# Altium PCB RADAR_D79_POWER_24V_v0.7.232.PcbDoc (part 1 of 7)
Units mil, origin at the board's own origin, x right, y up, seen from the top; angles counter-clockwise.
Board outline 3110.24 x 3110.24 mil, 8 copper layers (Top Layer, GND1, SIG1, PWR1, PWR2, SIG2, GND2, Bottom Layer), stack 55.2 mil thick; 304 components, 269 nets, 1408 pads, 1367 vias.
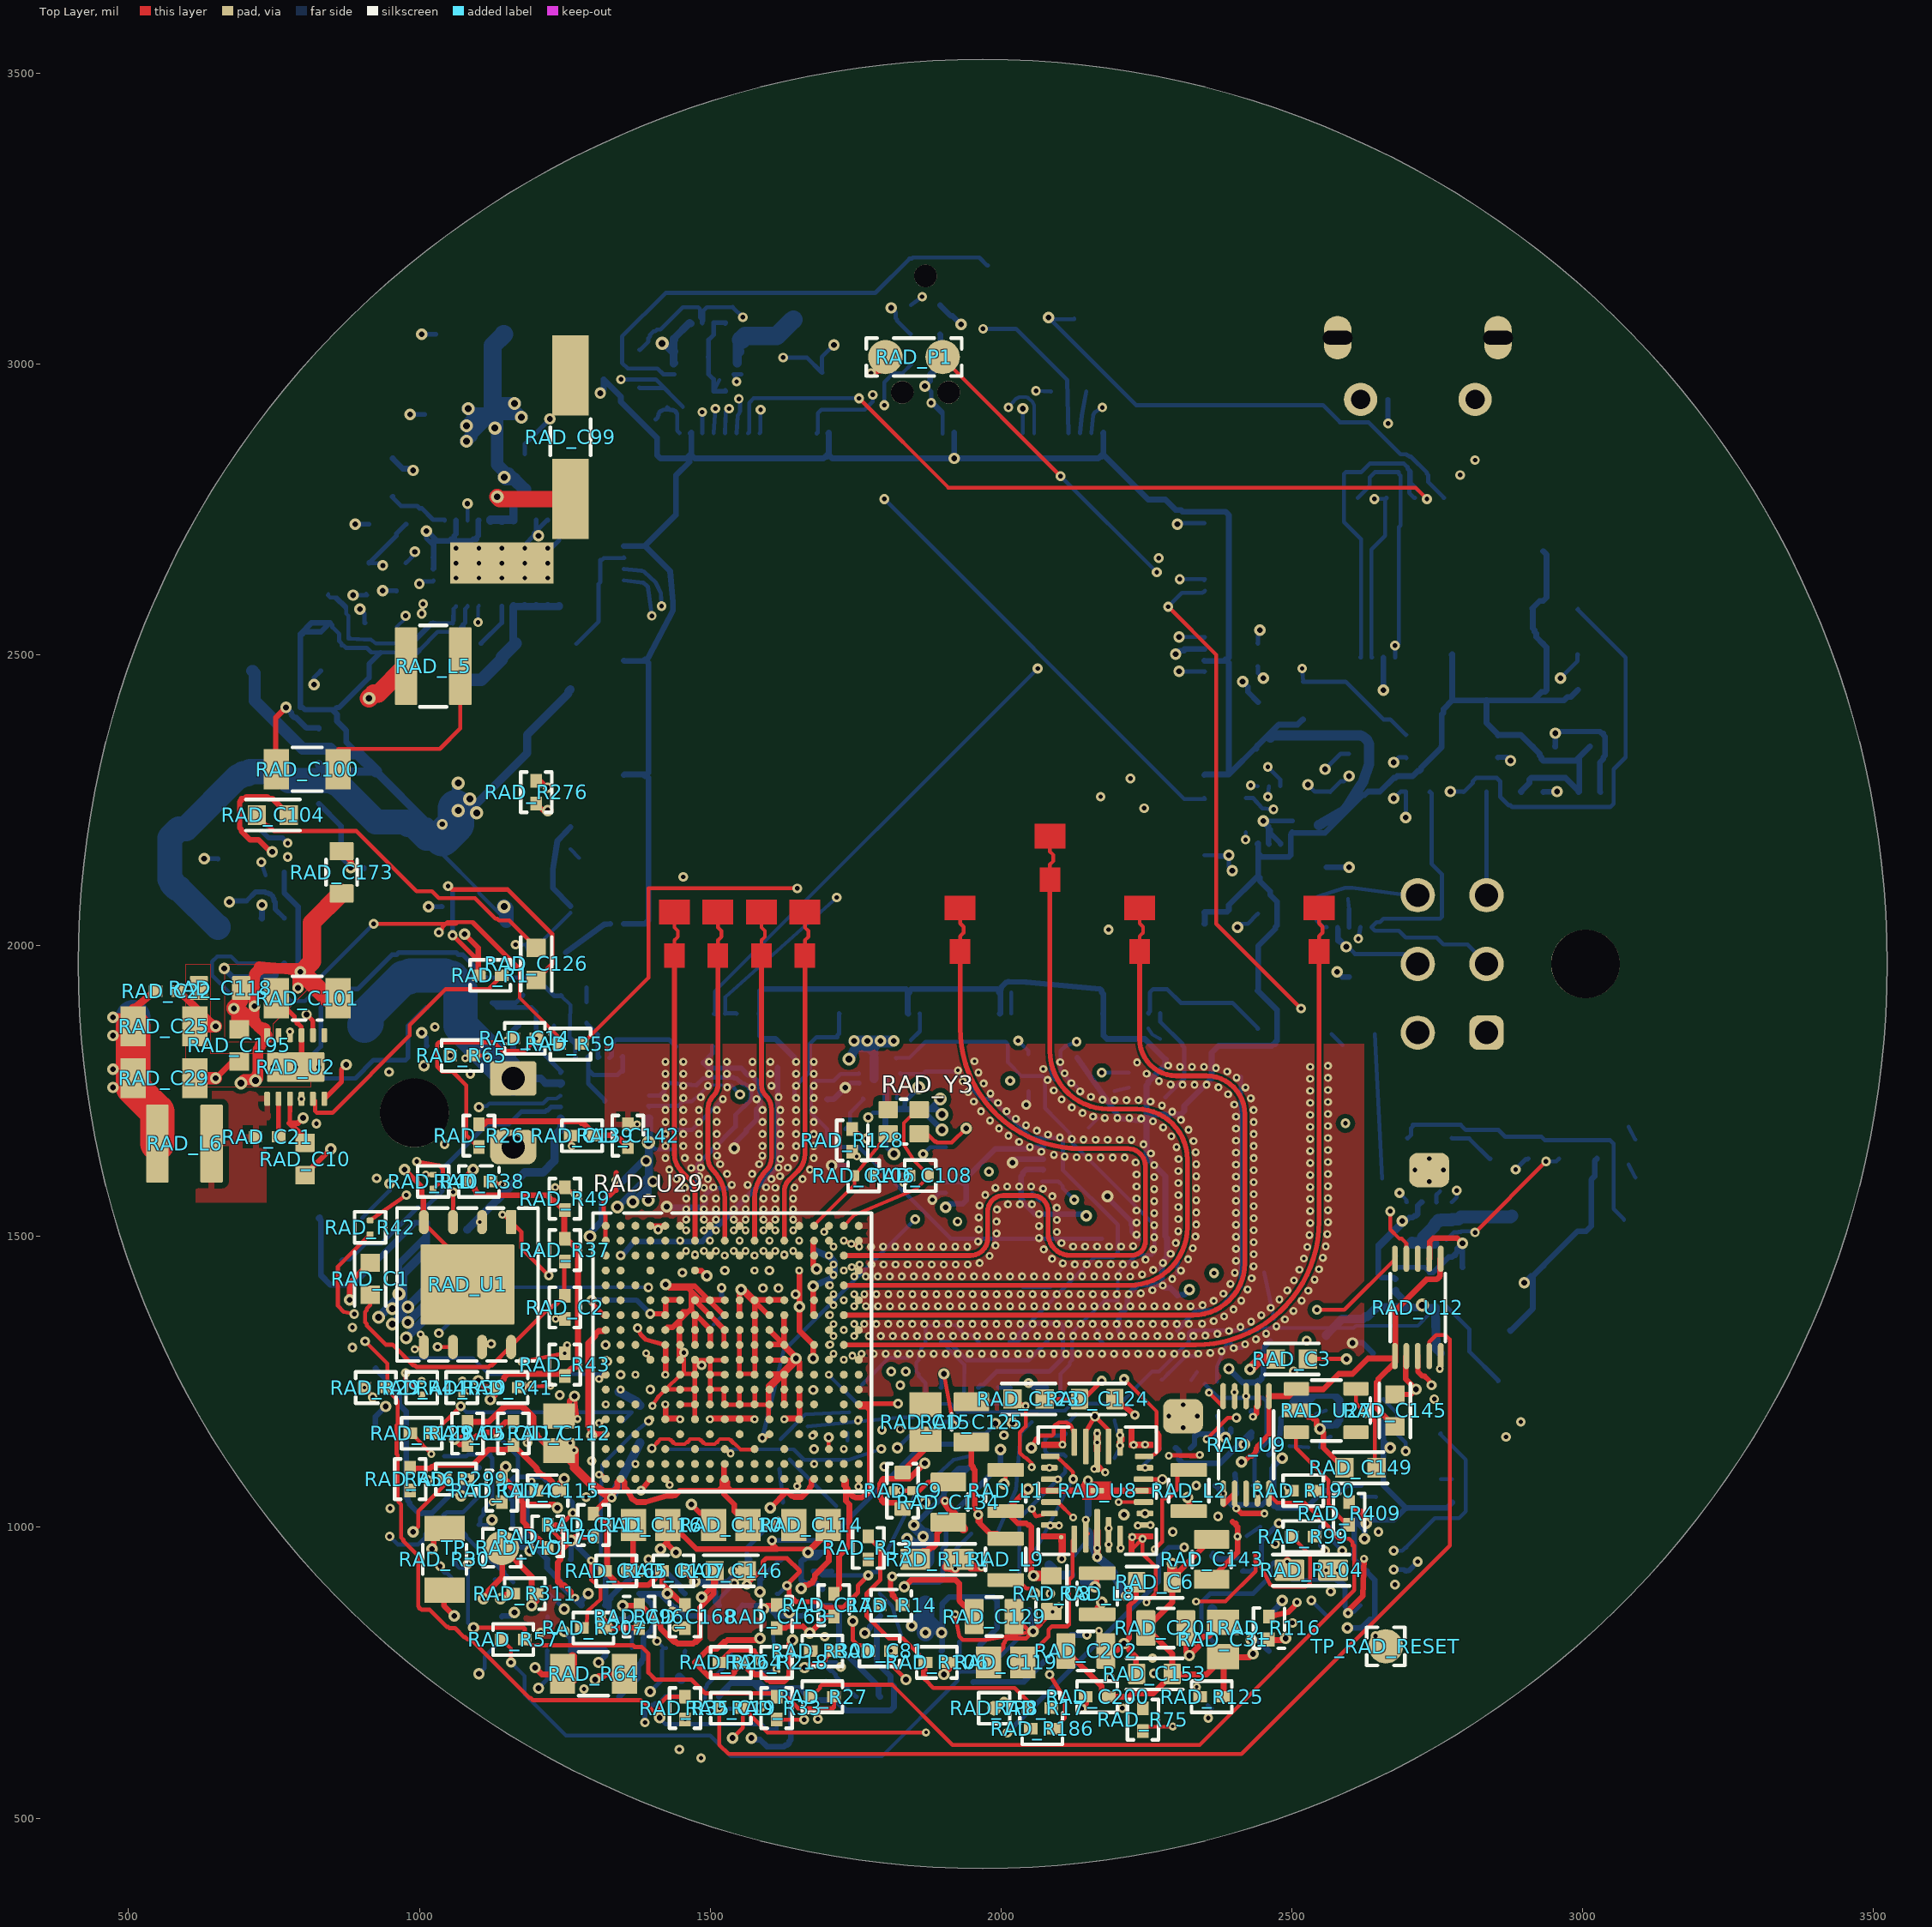
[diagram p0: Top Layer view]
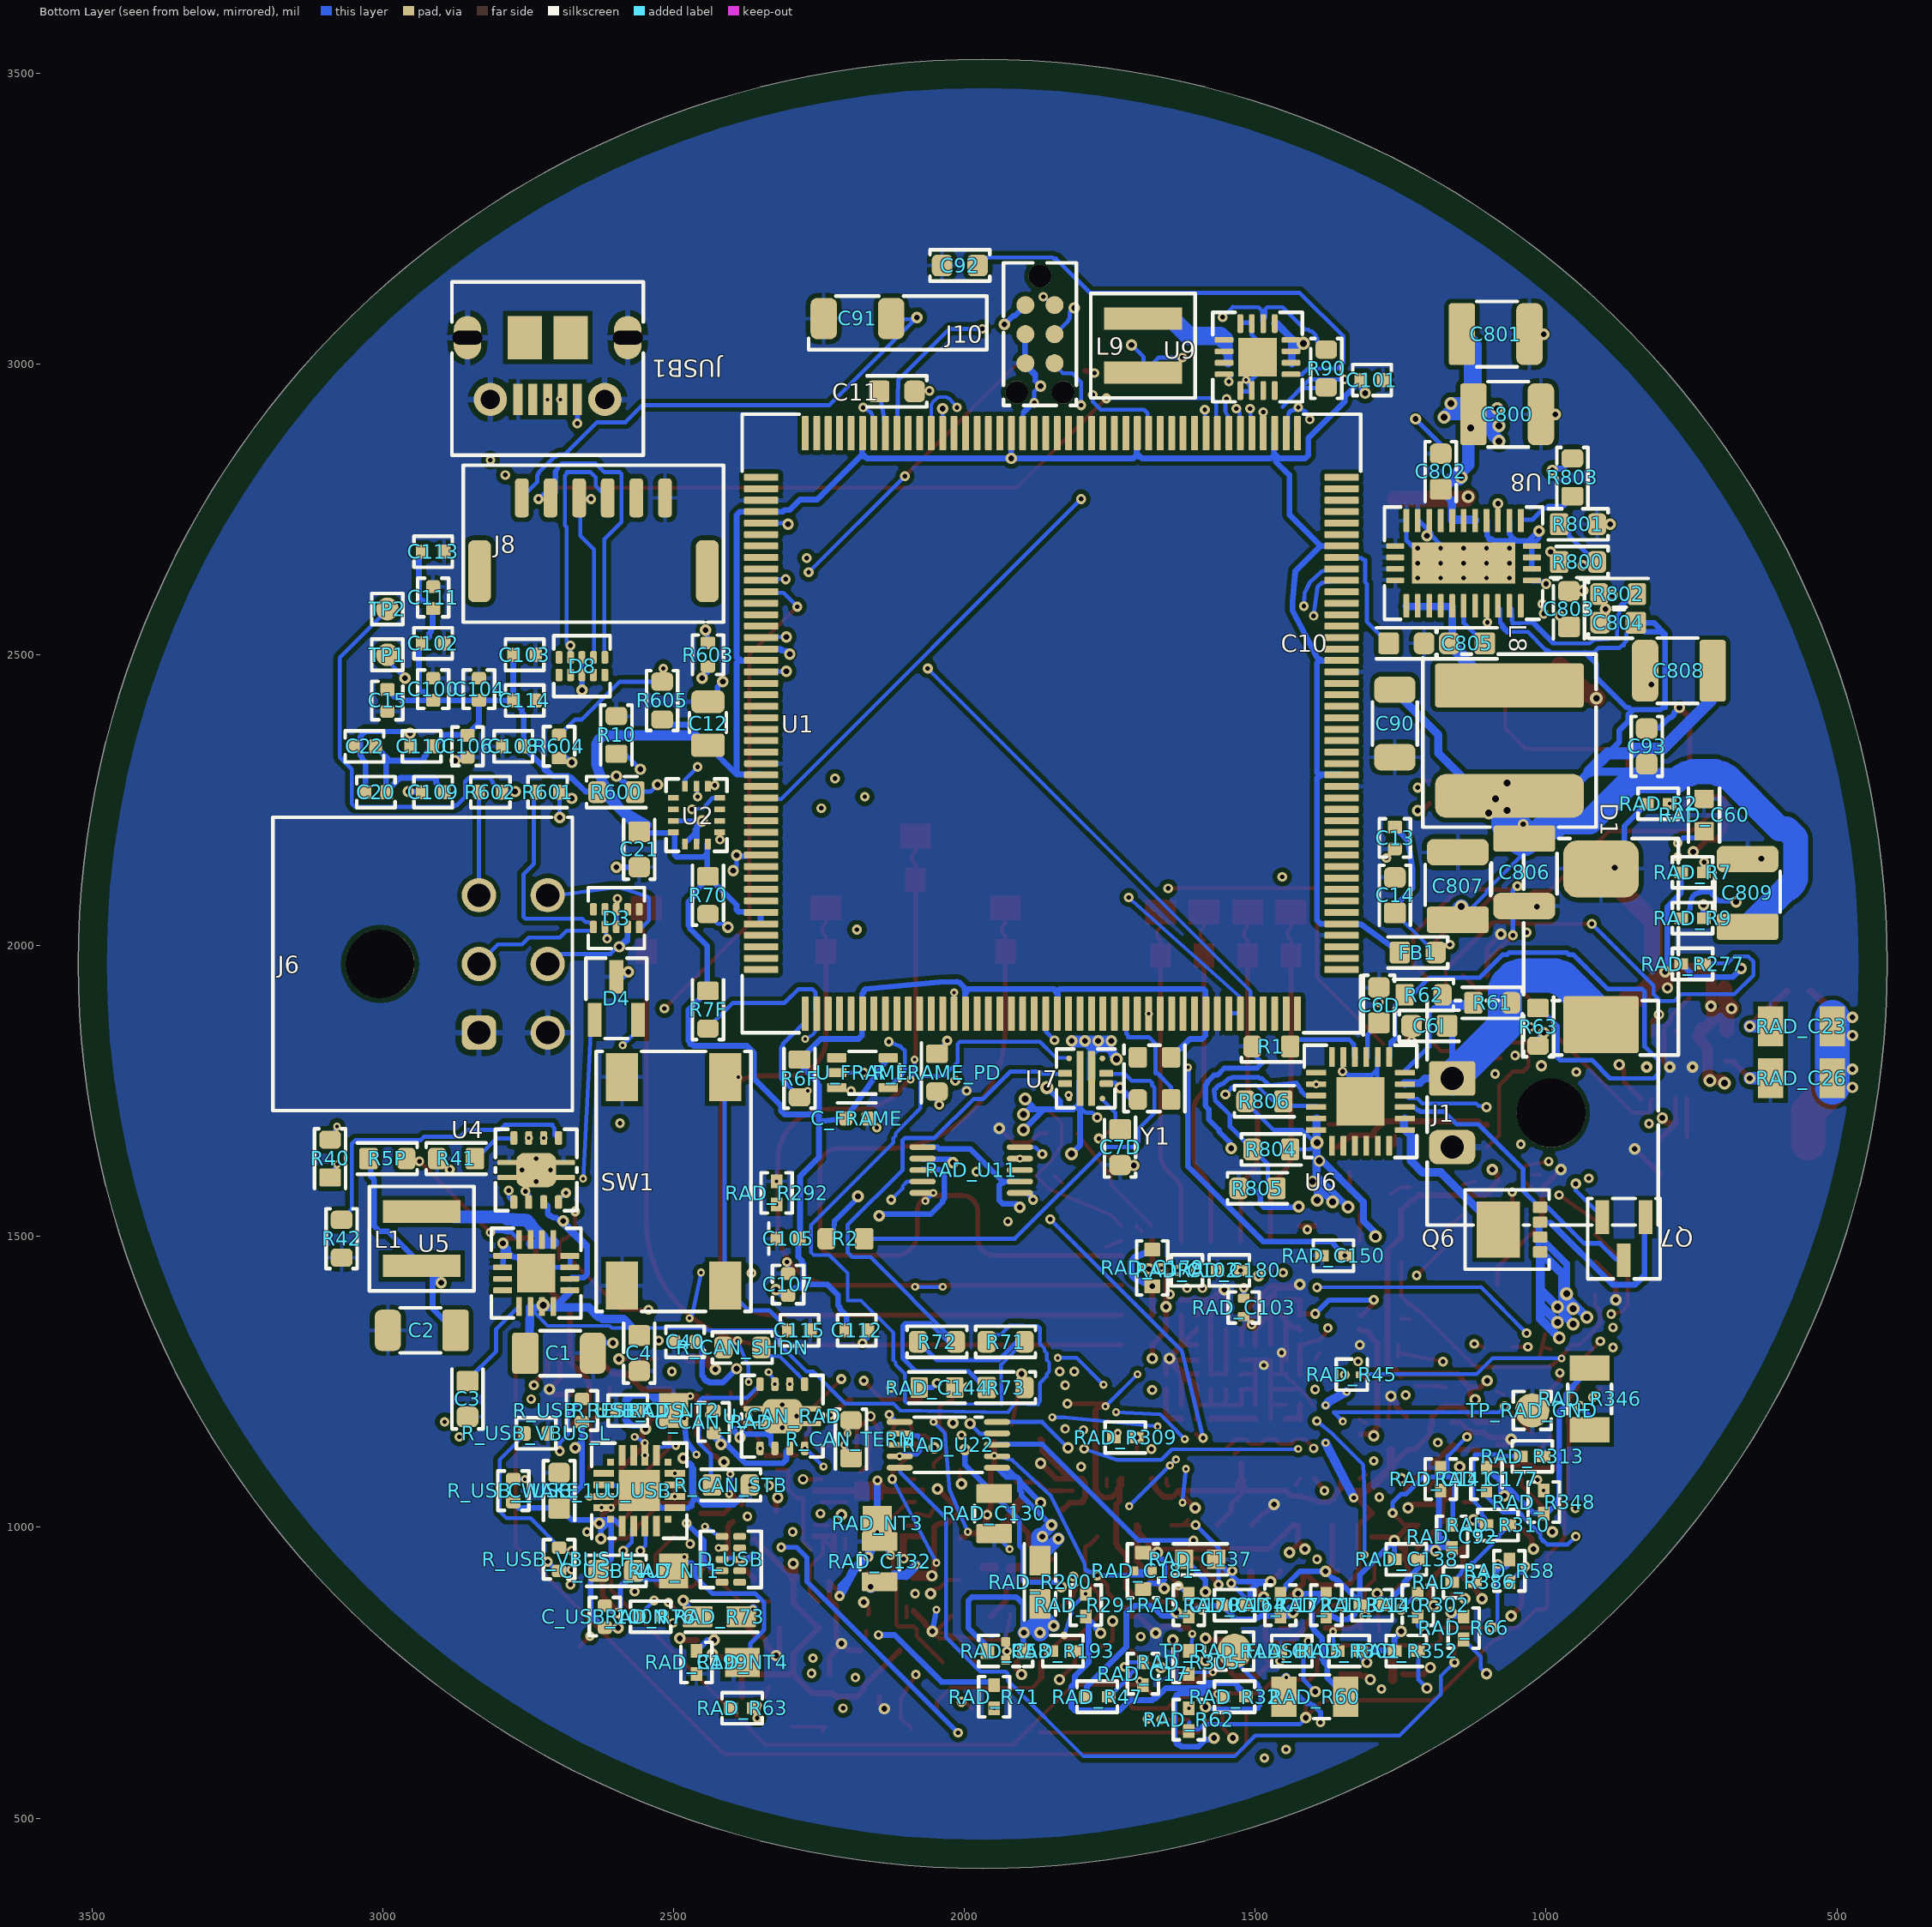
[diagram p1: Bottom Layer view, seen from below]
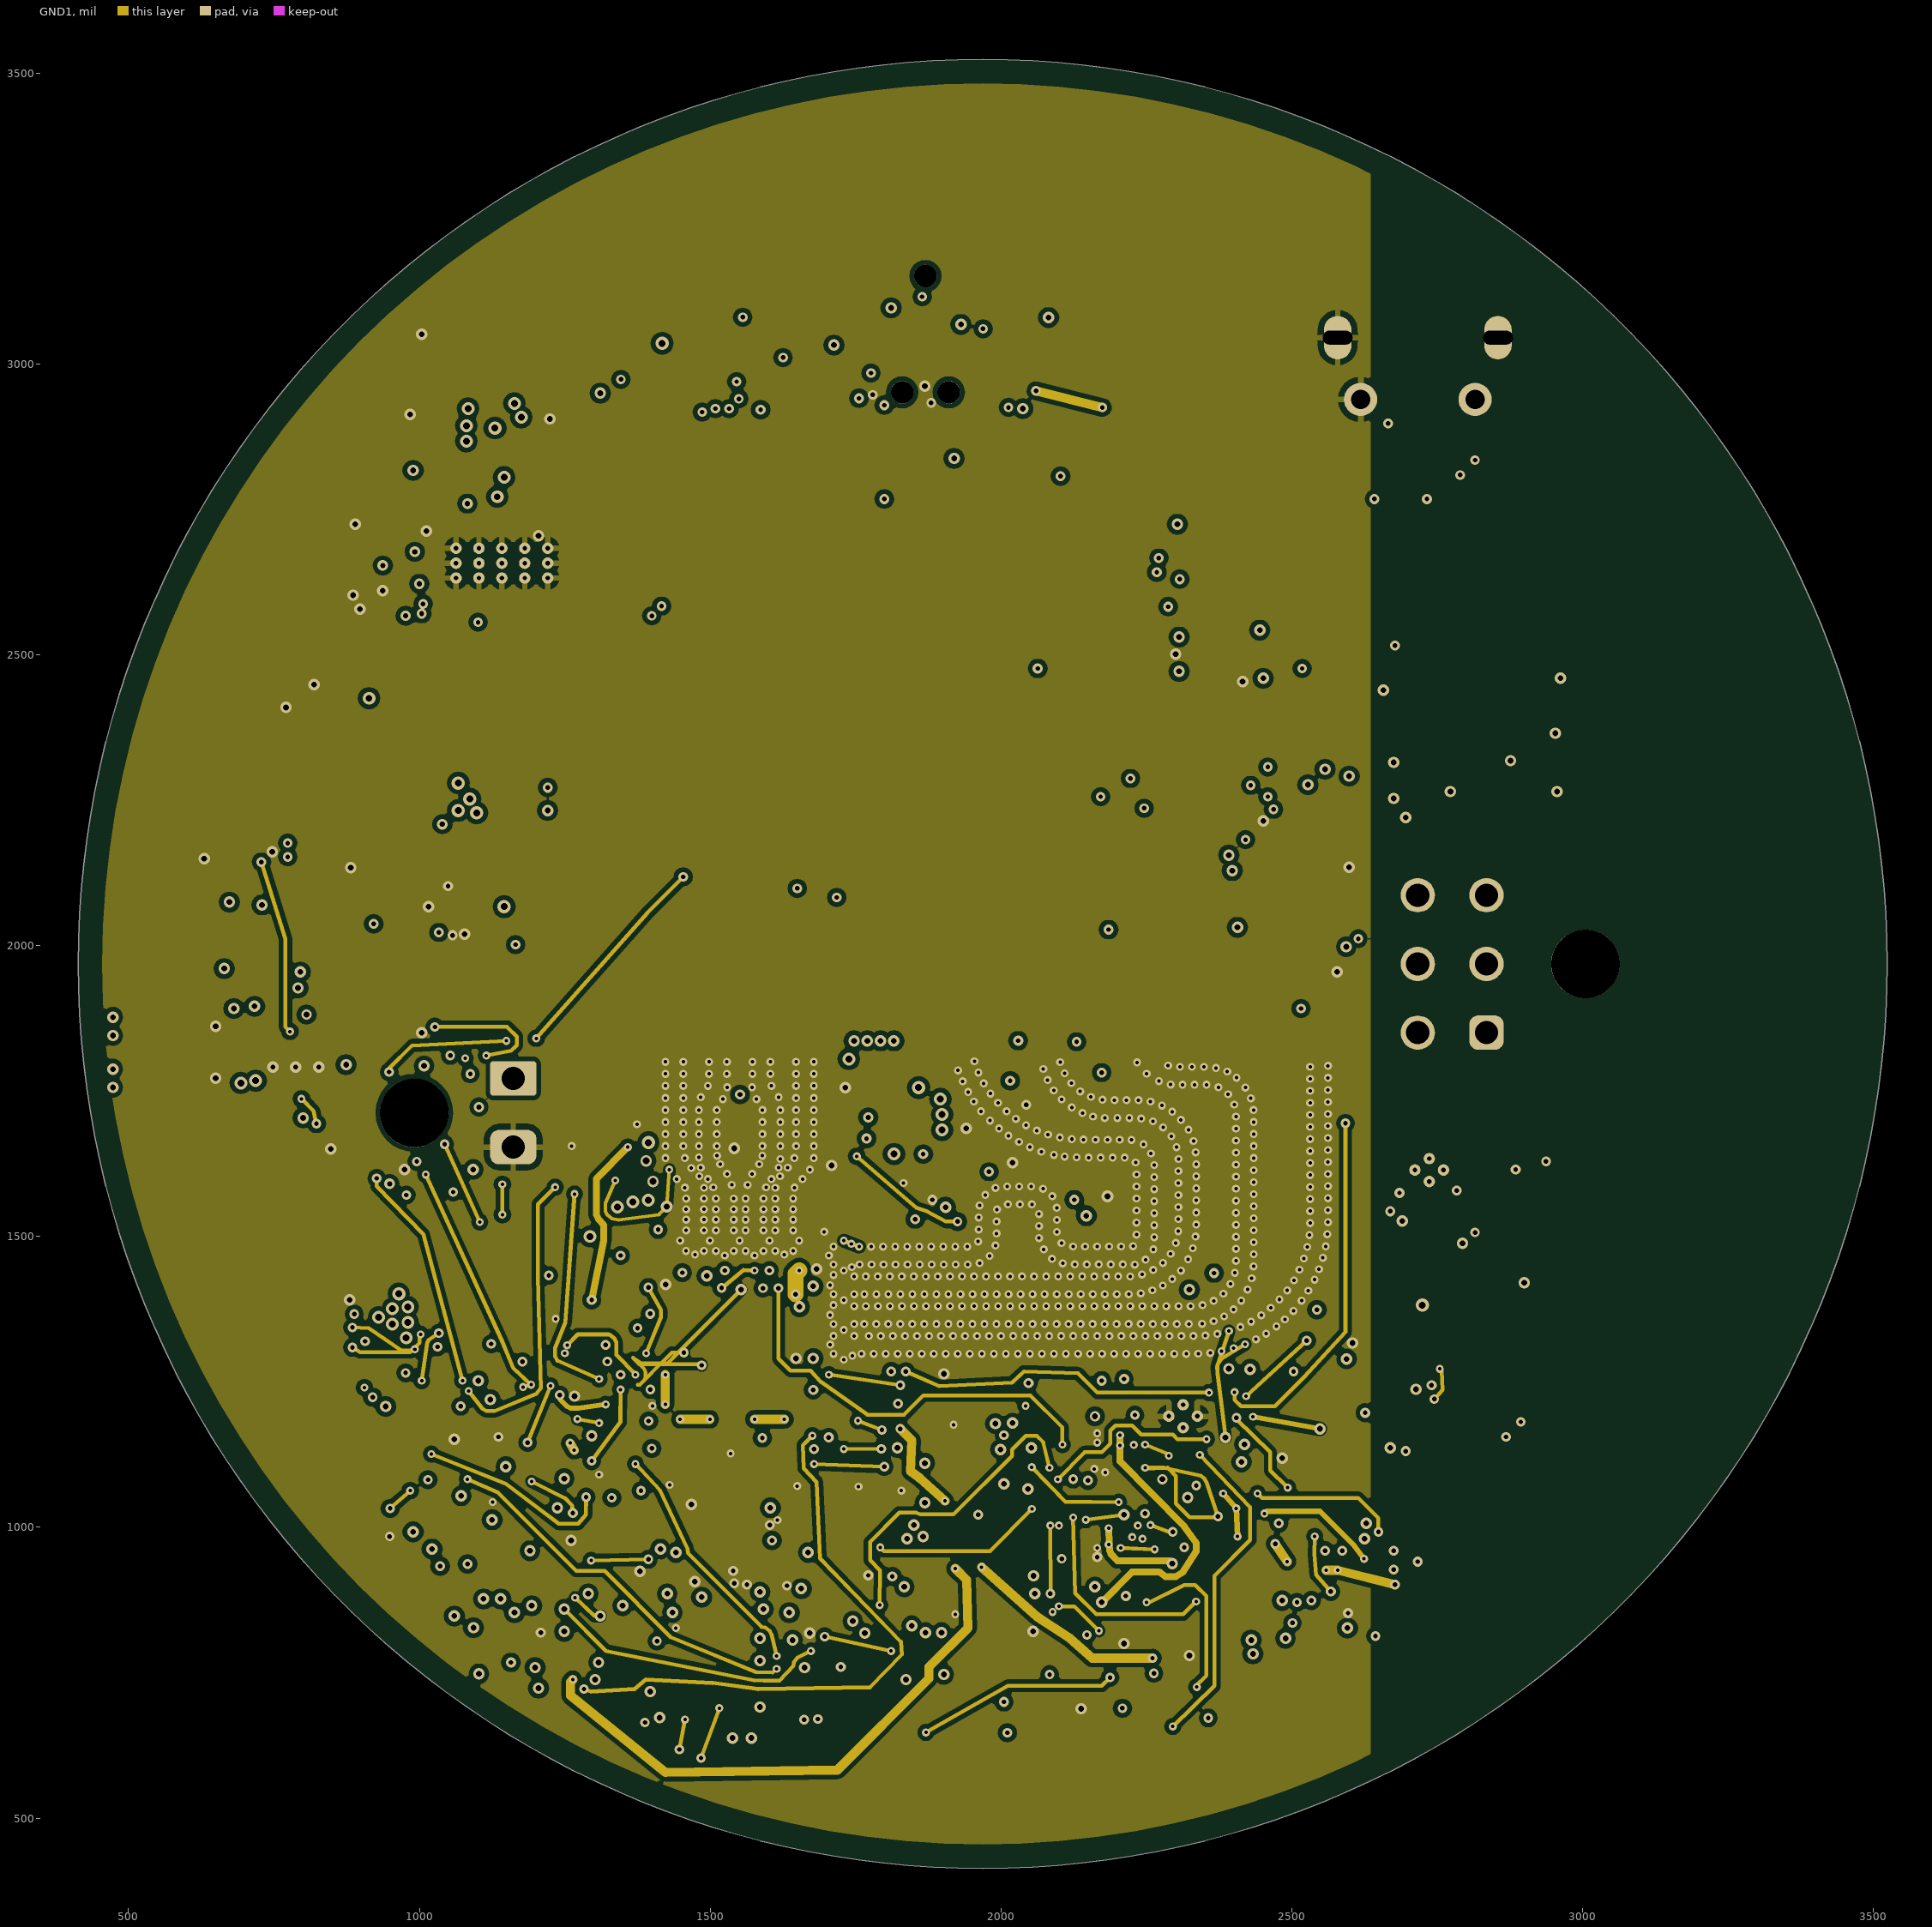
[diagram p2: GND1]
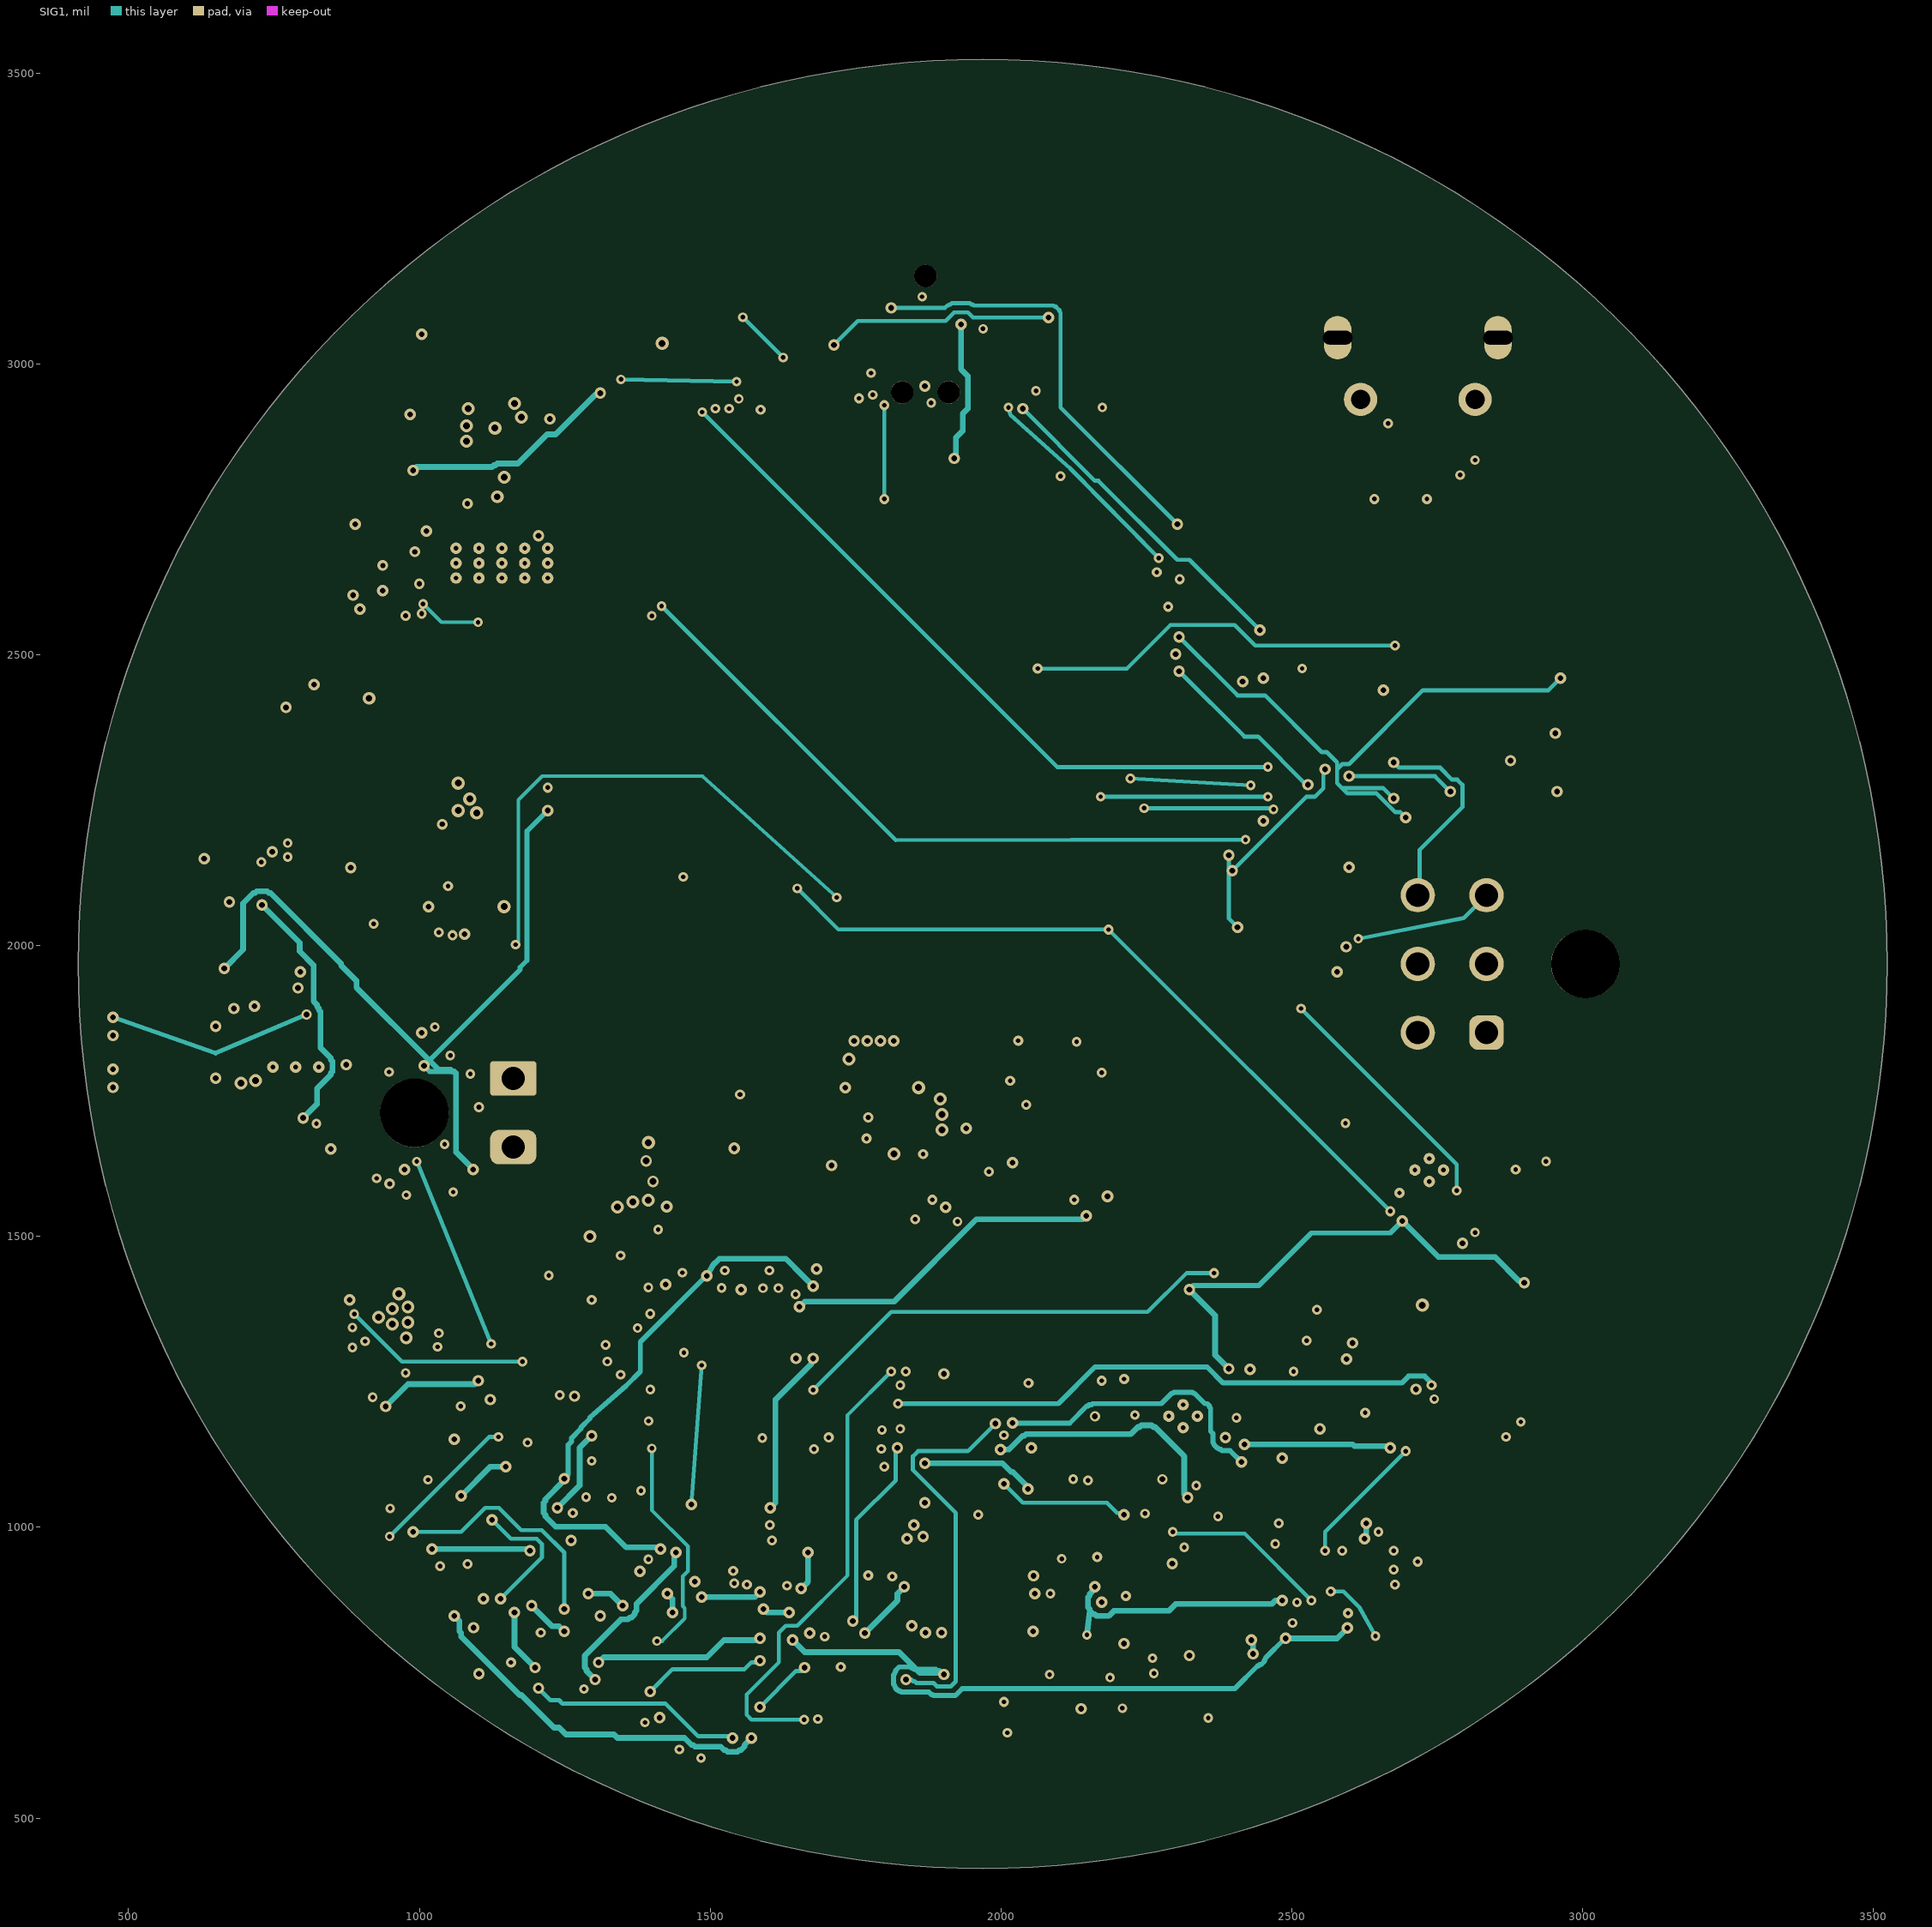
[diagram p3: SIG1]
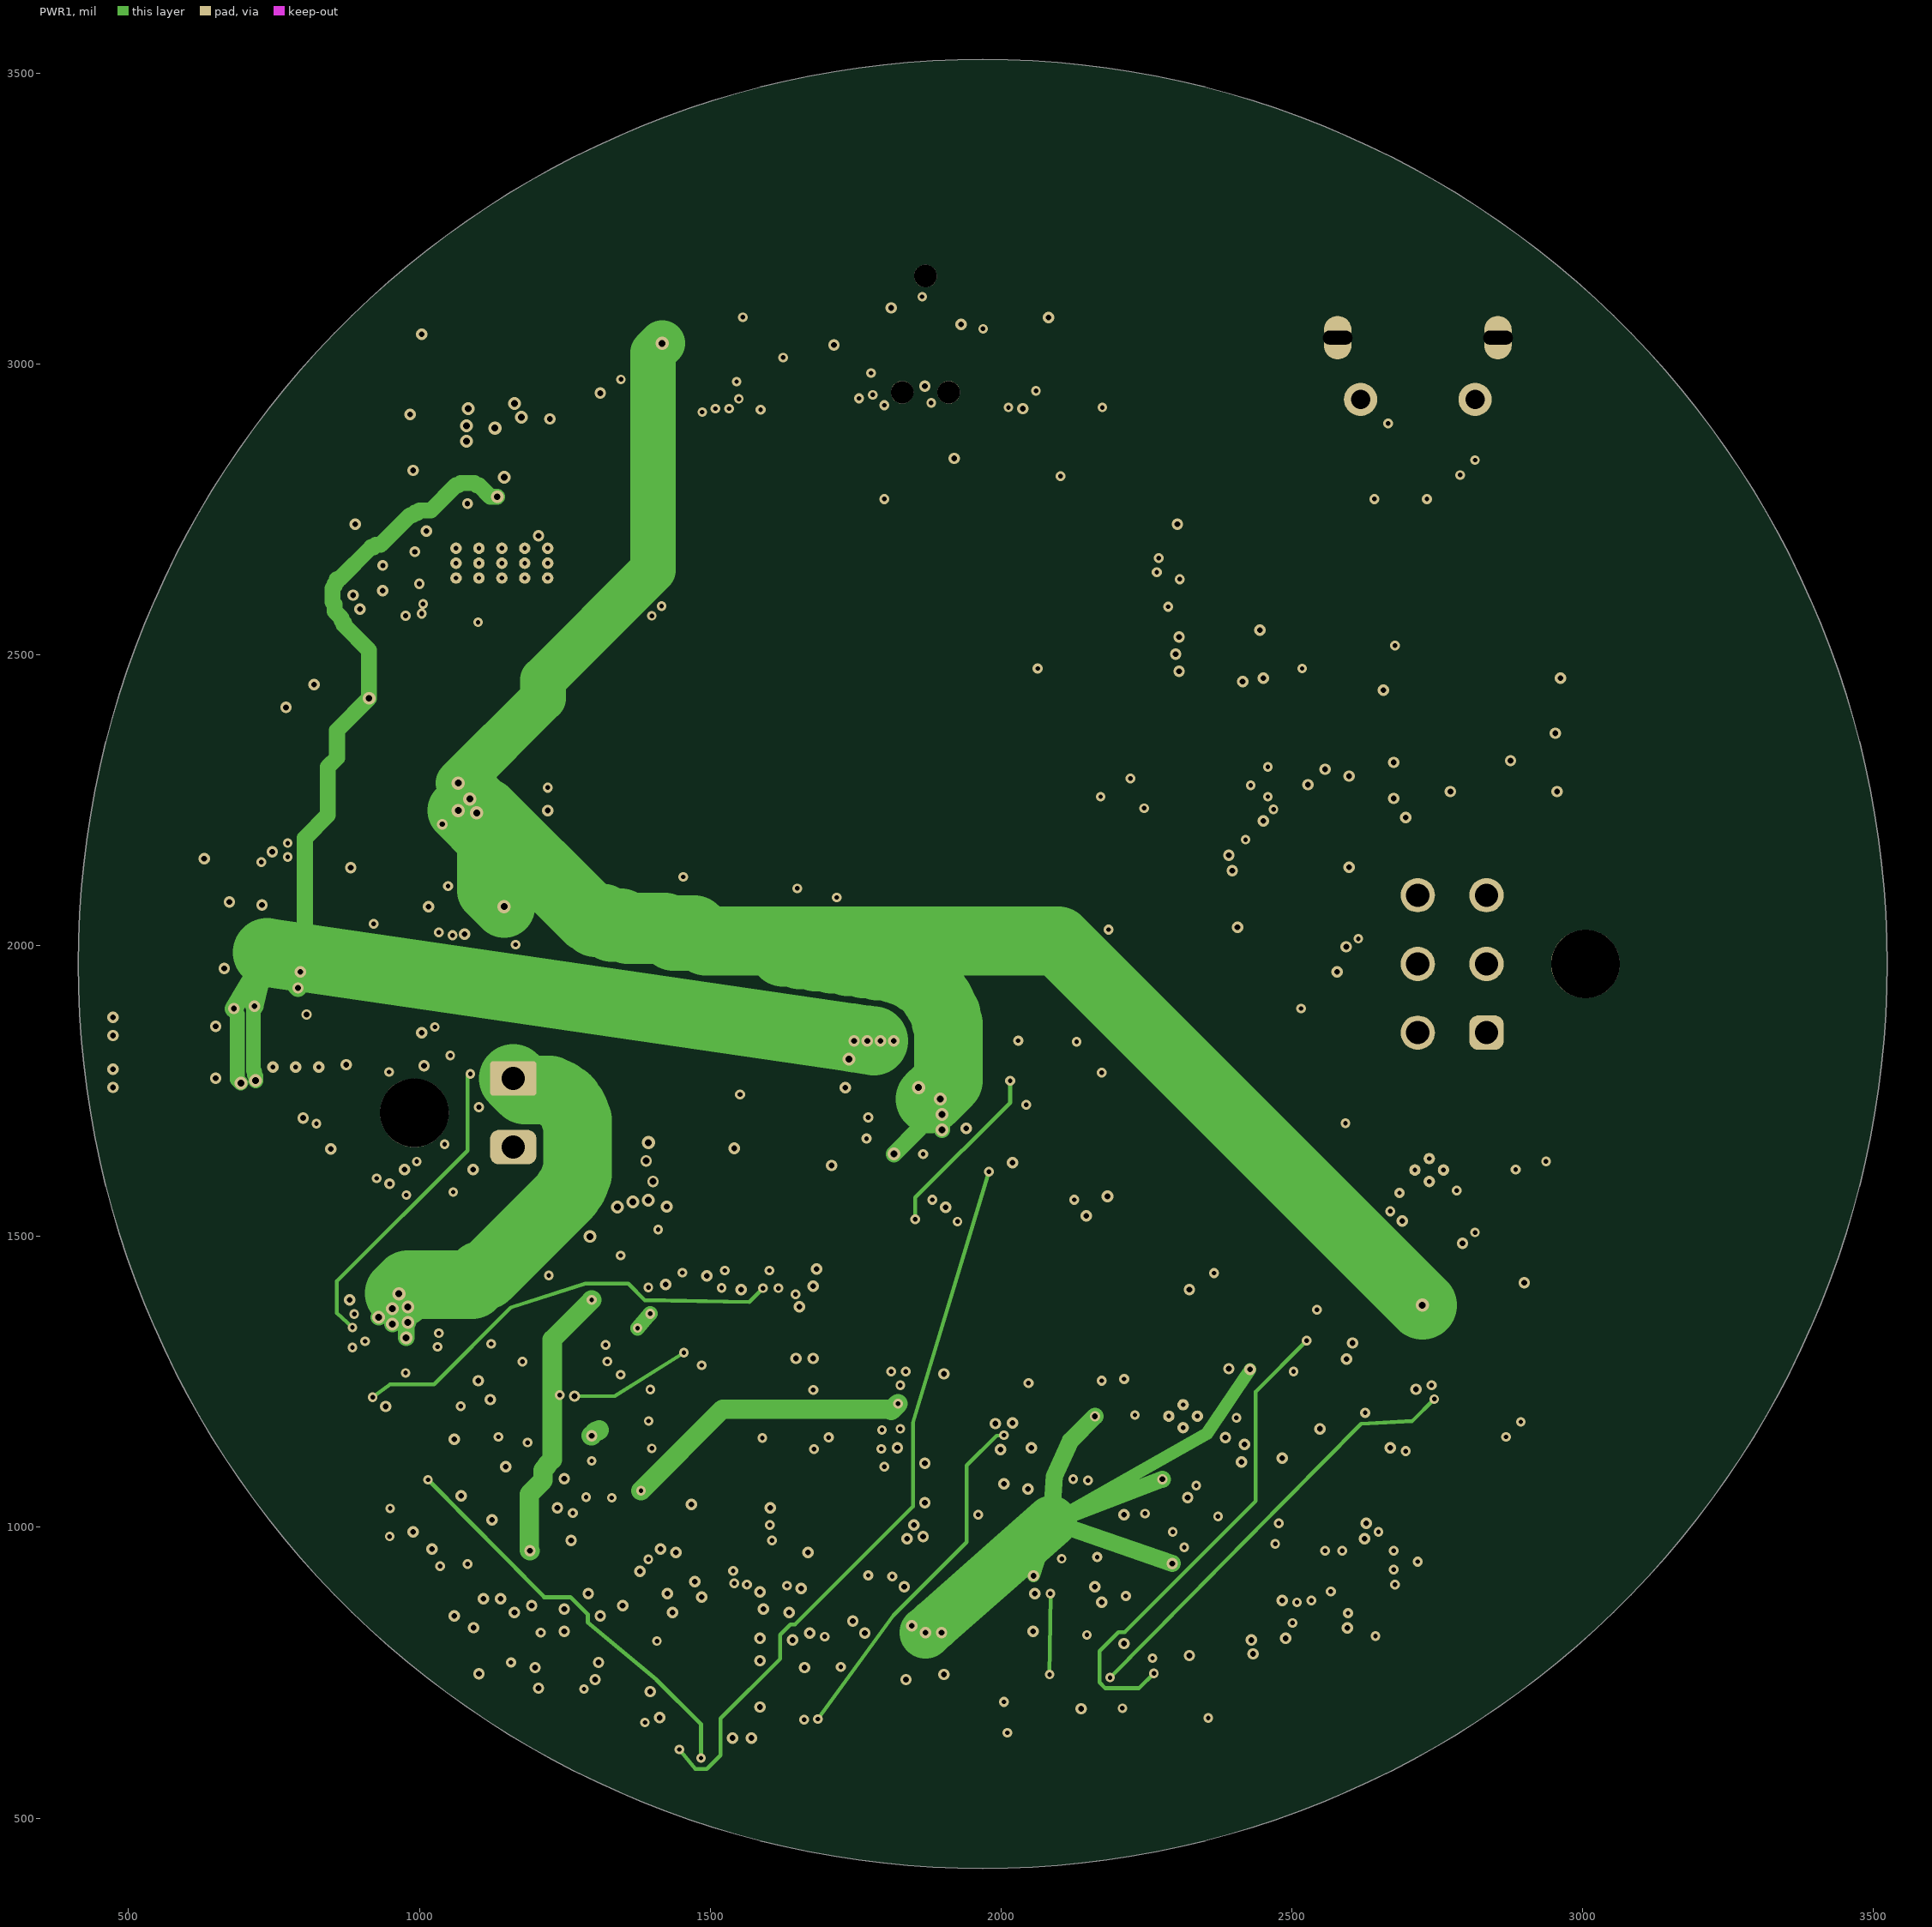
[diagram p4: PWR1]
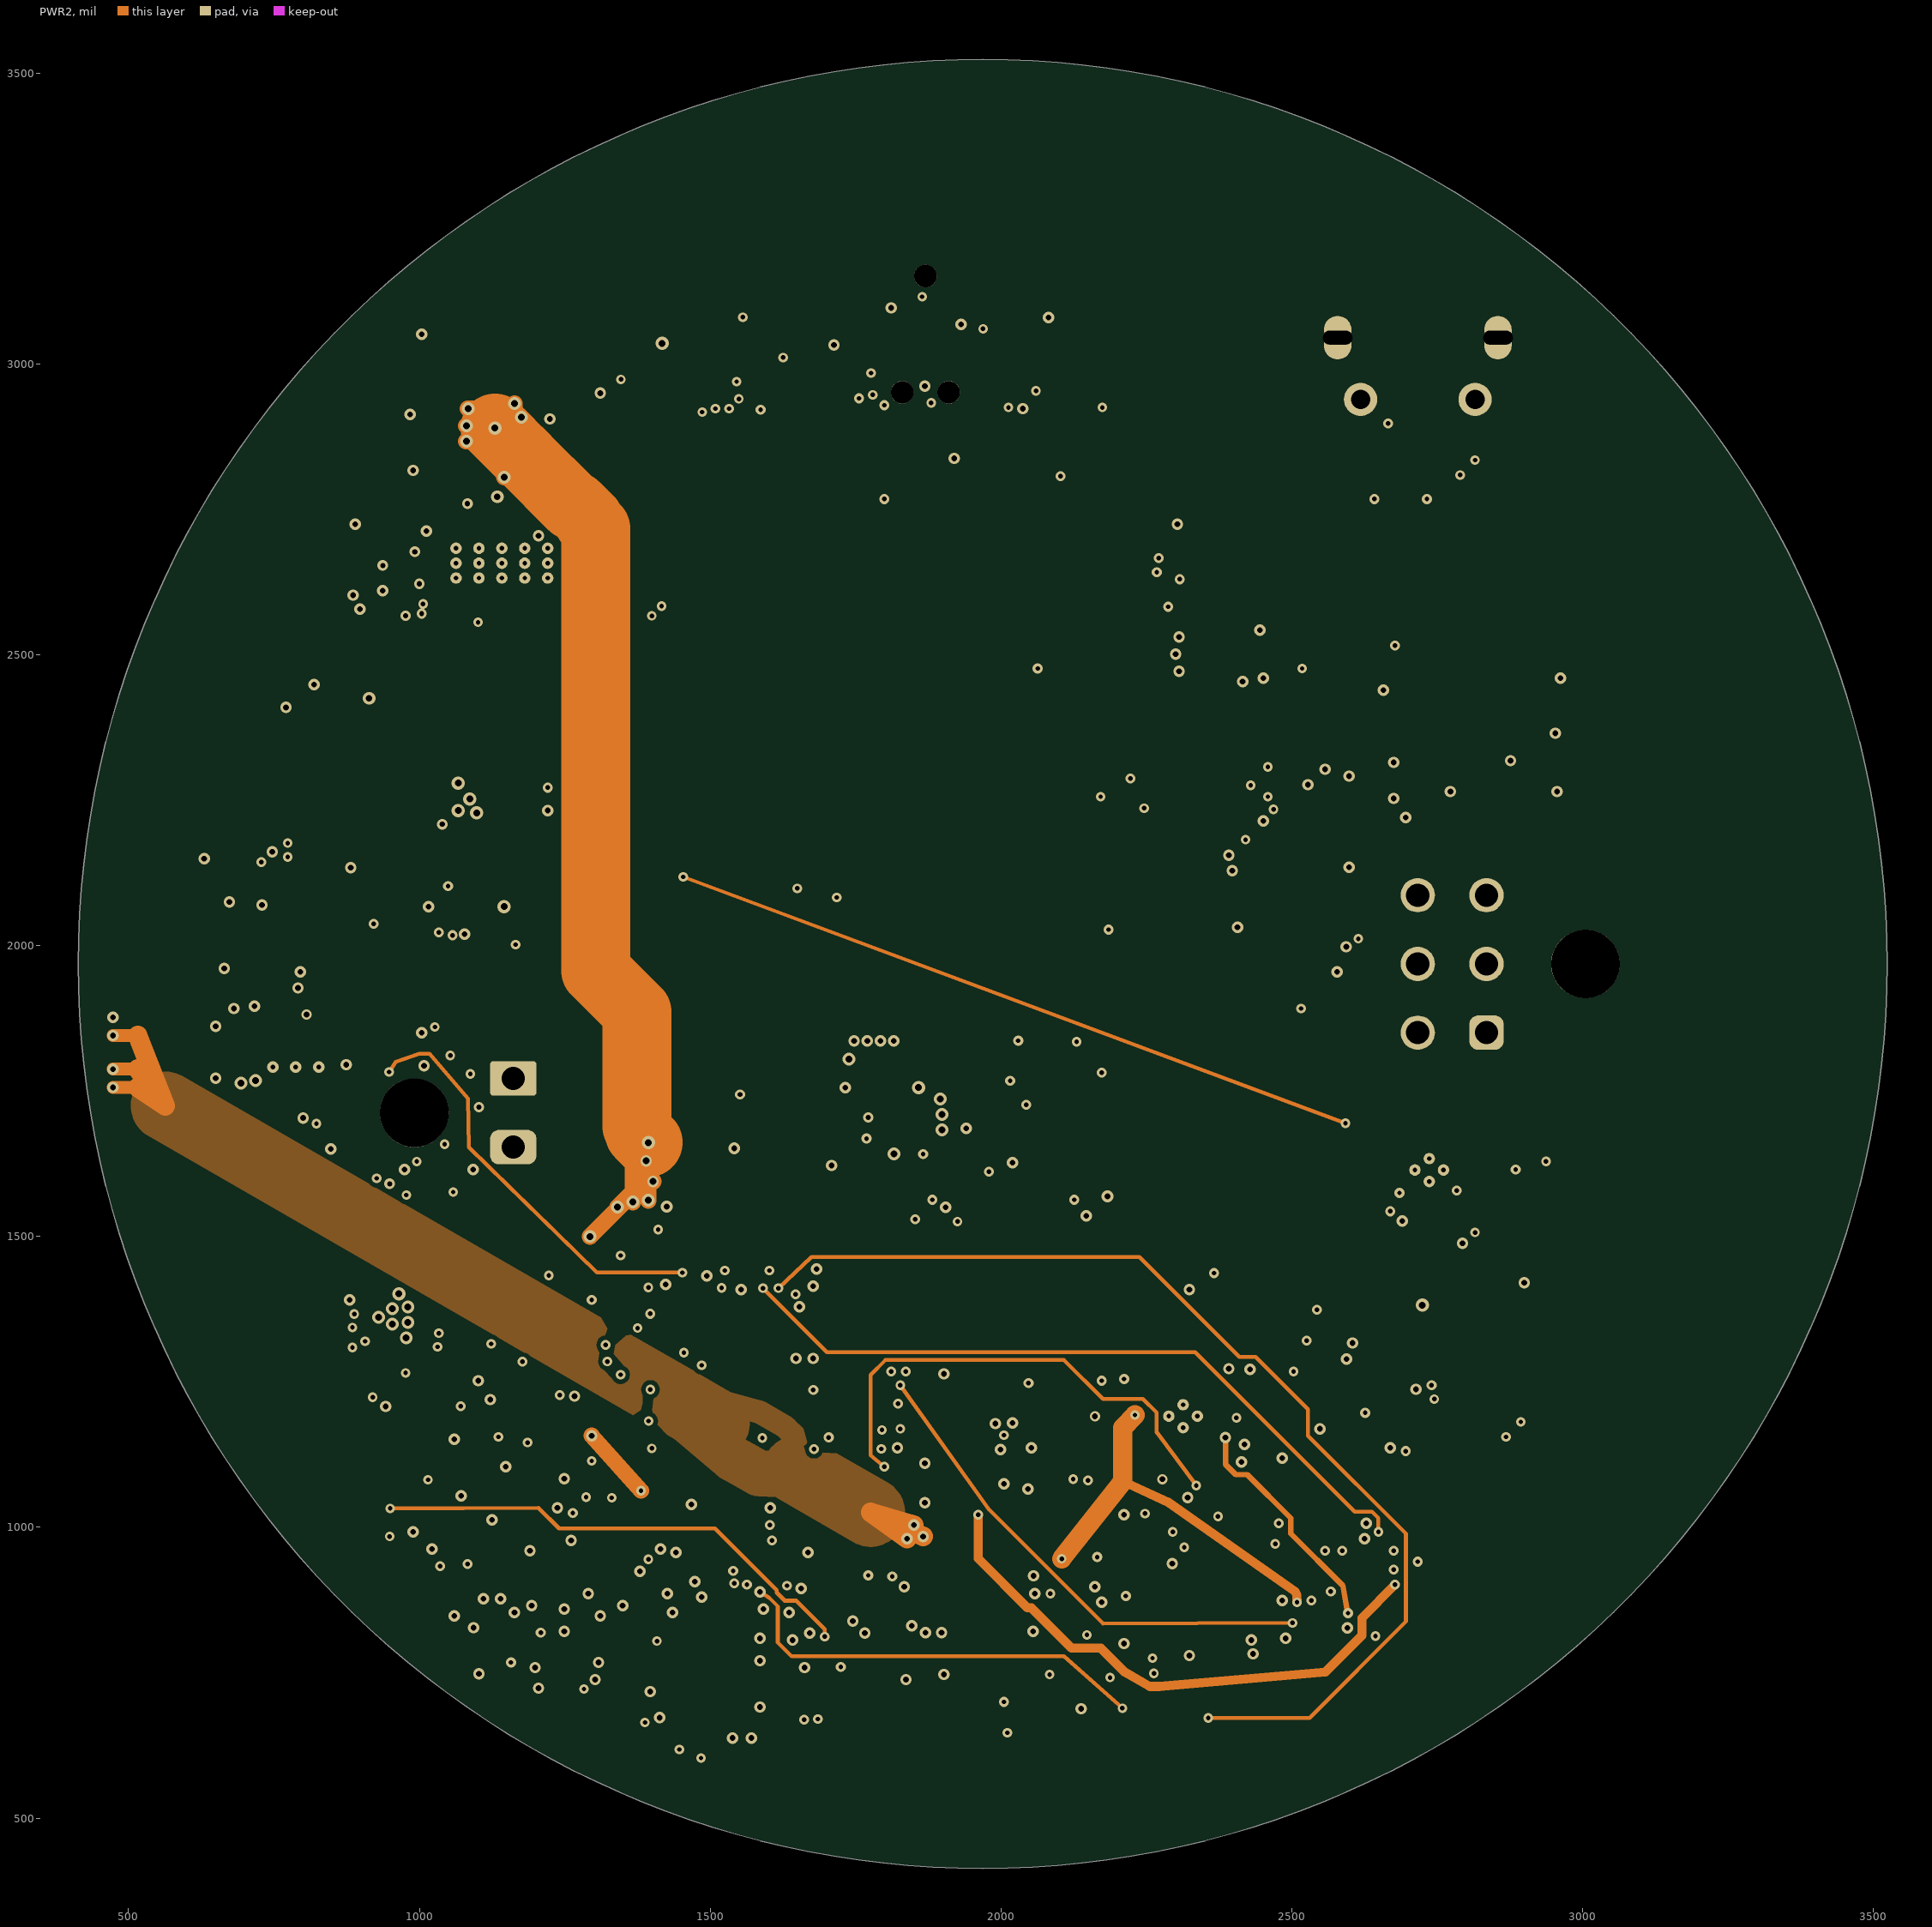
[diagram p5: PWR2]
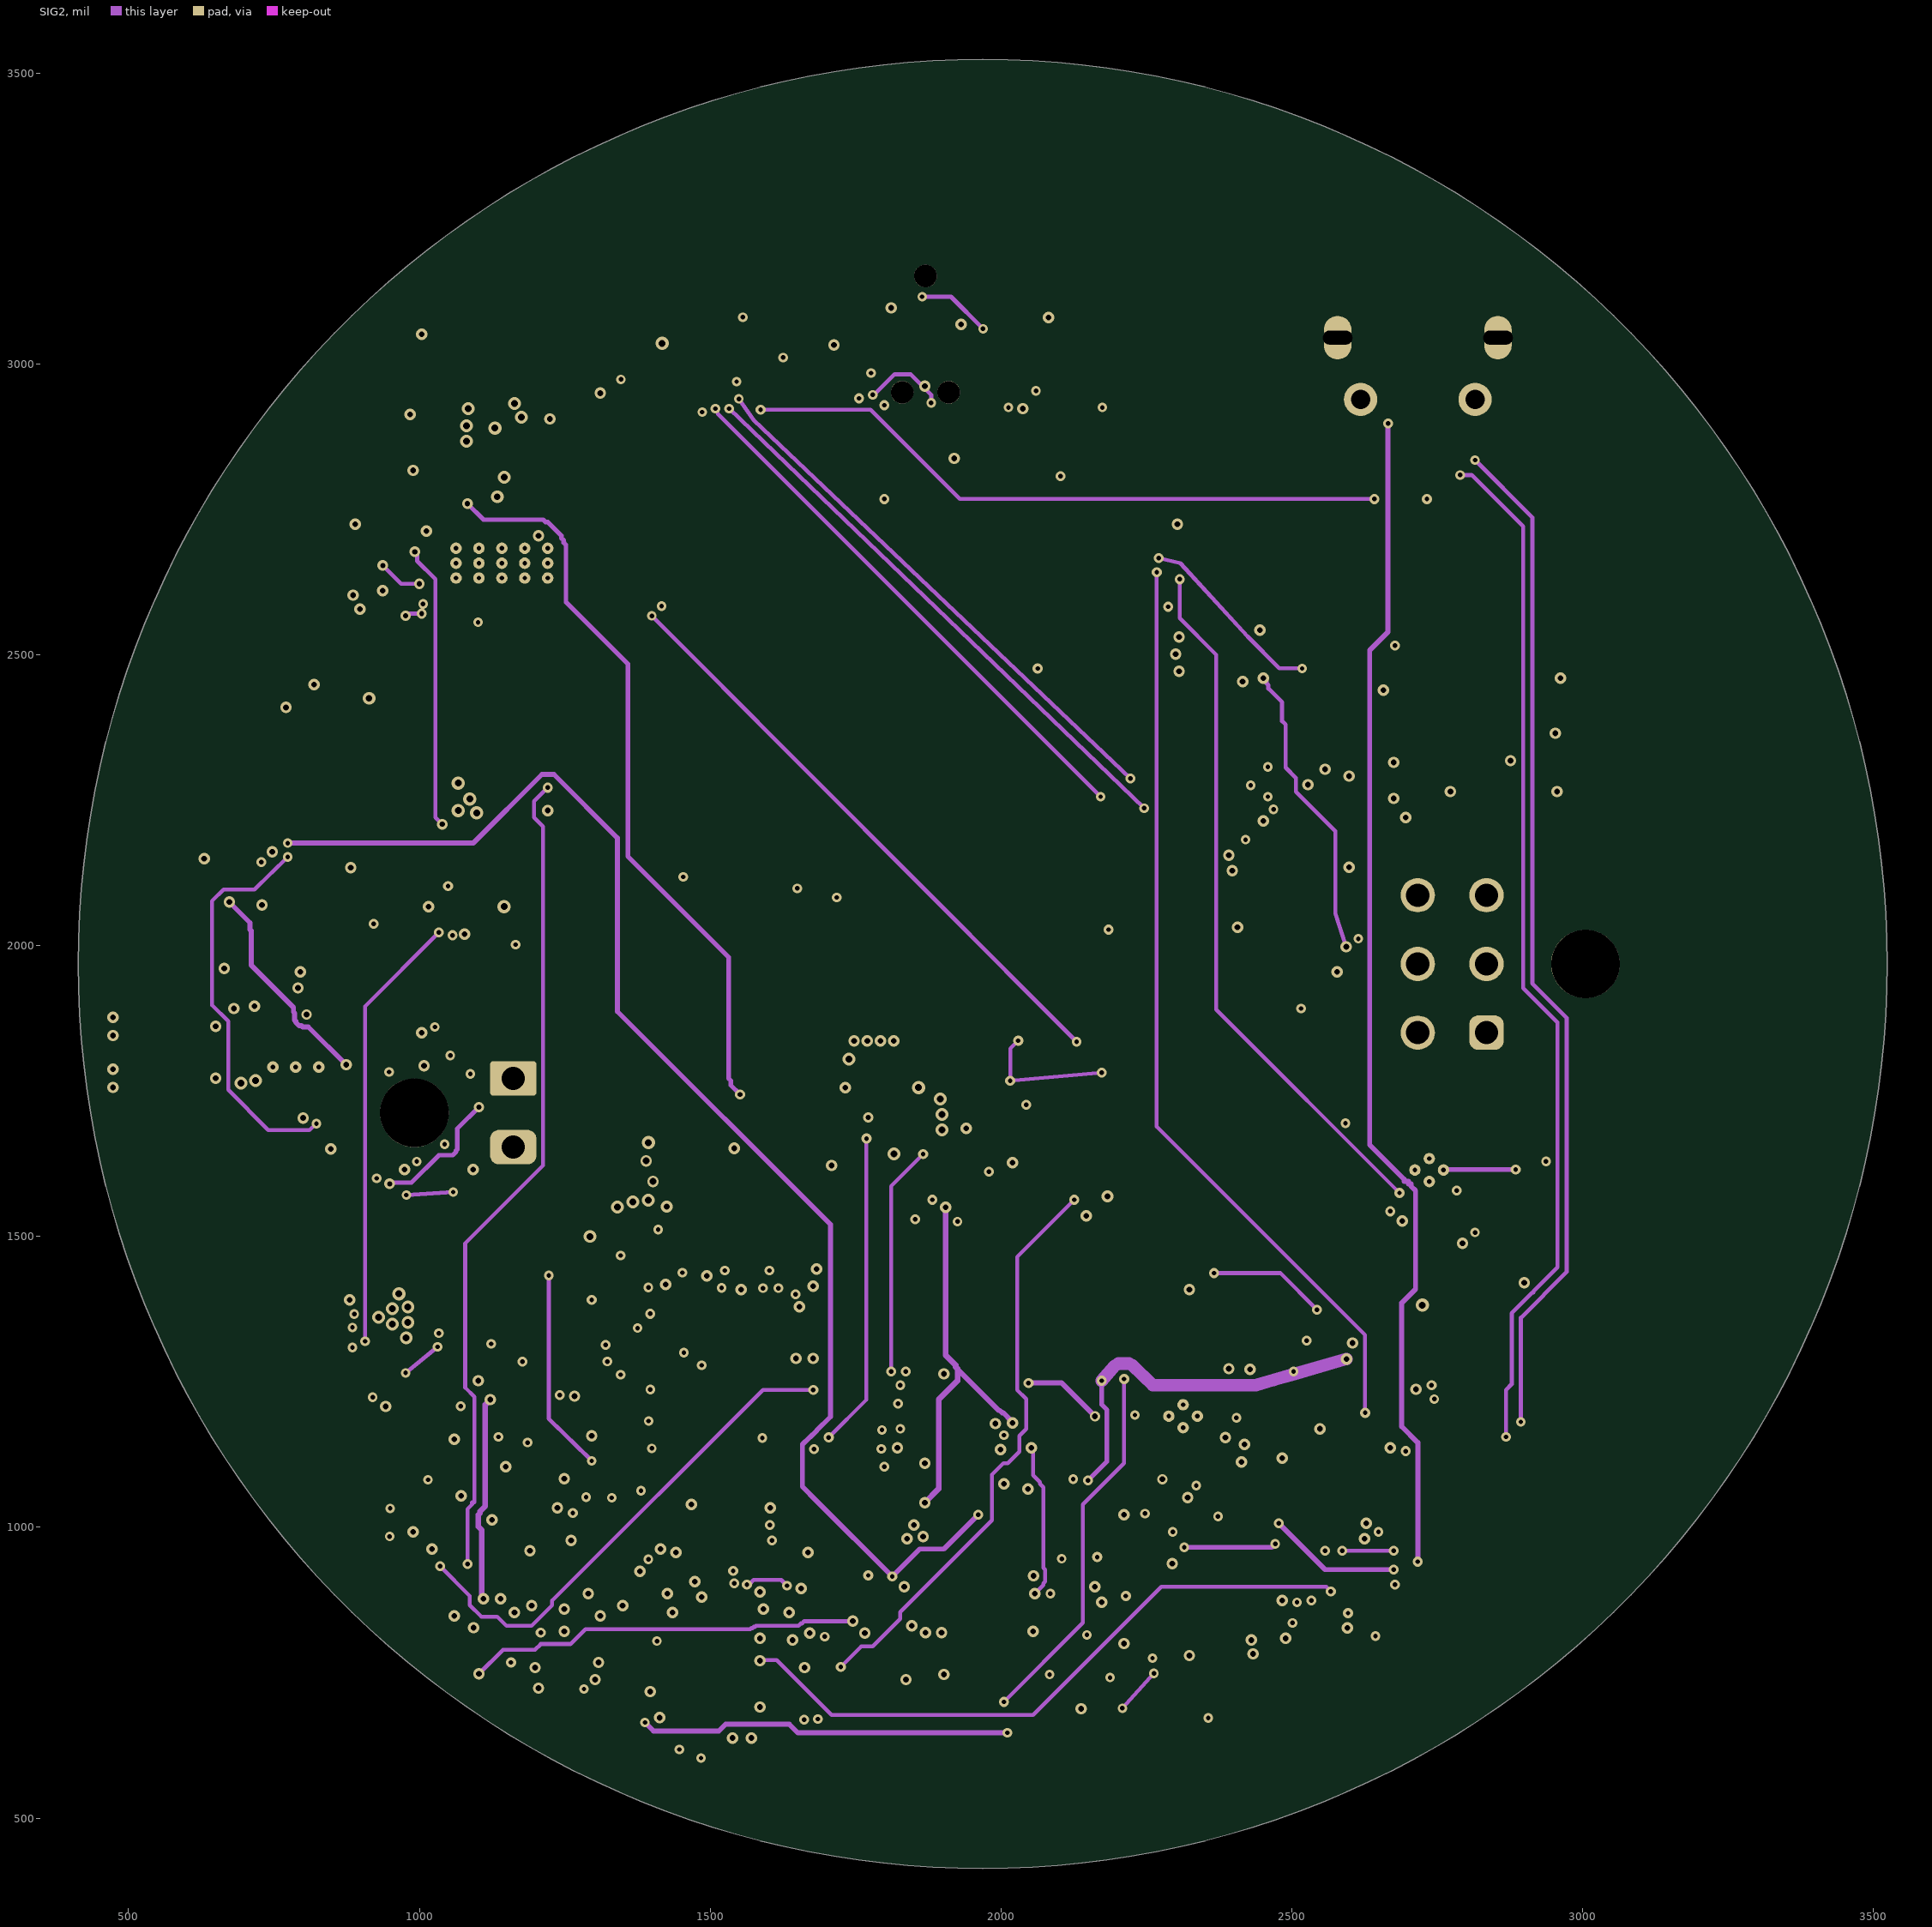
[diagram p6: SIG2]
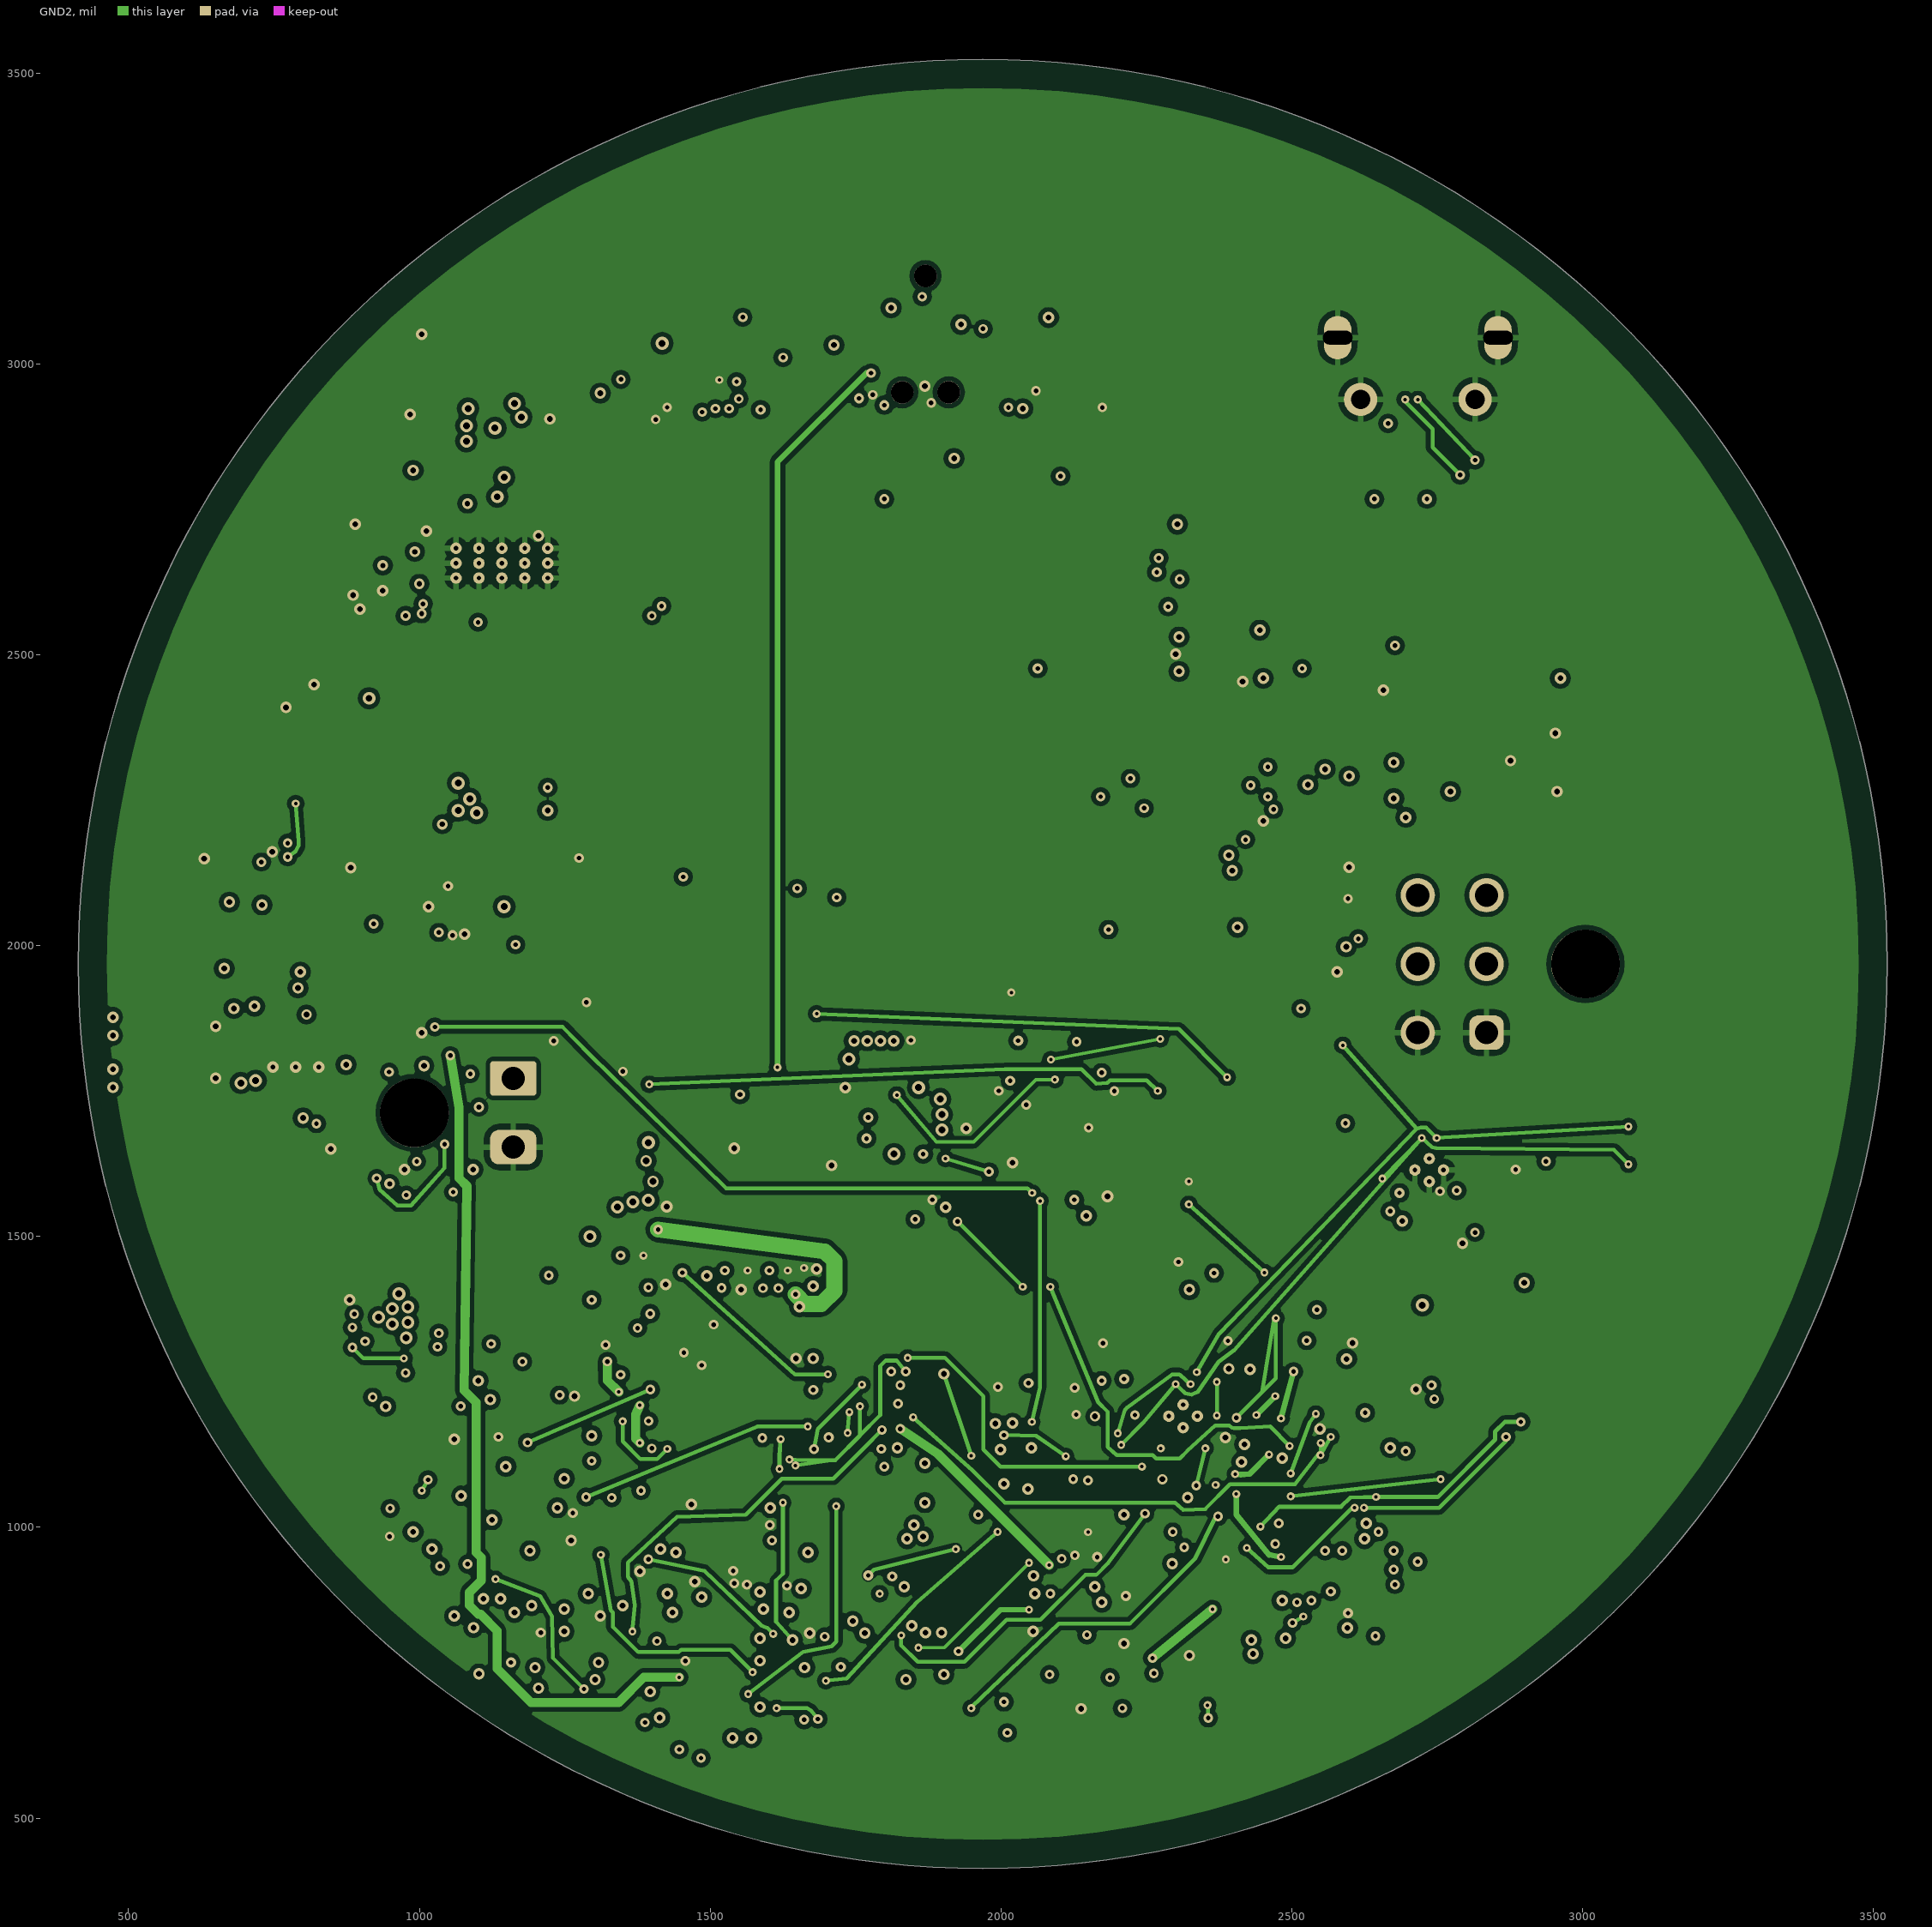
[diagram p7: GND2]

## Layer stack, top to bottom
Top Solder: solder mask 0.8, Solder Resist, Dk 3.5
Top Layer: signal copper 1.6
Dielectric 1: prepreg 5, RO3003, Dk 3
GND1: signal copper 1.4
Dielectric 2: core 5, FR-4 High Tg, Dk 4.04
SIG1: signal copper 0.7
Dielectric 3: prepreg 10, FR-4 High Tg, Dk 4.04
PWR1: signal copper 1.4
Dielectric 4: prepreg 5, FR-4 High Tg, Dk 4.04
PWR2: signal copper 1.4
Dielectric 5: prepreg 10, FR-4 High Tg, Dk 4.04
SIG2: signal copper 0.7
Dielectric 6: core 5, FR-4 High Tg, Dk 4.04
GND2: signal copper 1.4
Dielectric 7: prepreg 5, FR-4 High Tg, Dk 4.04
Bottom Layer: signal copper 1.6
Bottom Solder: solder mask 0.8, Solder Resist, Dk 3.5

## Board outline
1968.5,413.39 cw(c1968.5,1968.5) 413.39,1968.5 cw(c1968.5,1968.5) 1968.5,3523.62 cw(c1968.5,1968.5) 3523.62,1968.5 cw(c1968.5,1968.5)

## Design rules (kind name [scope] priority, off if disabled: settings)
Clearance PROC194A_RF_TOP_TO_GND_VIA [OnLayer('Top Layer') AND (IsTrack OR IsArc) AND (InNet('TI_TX1') OR InNet('TI_TX2') OR InNet('TI_TX3') OR InNet('TI_TX4') OR InNet('TI_RX1') OR InNet('TI_RX2') OR InNet('TI_RX3') OR InNet('TI_RX4')) vs IsVia AND InNet('GND')] p1: gap=10 ignorepadtopadclearanceinfootprint=FALSE except(4: Arc-Via Arc-Hole Track-Via Track-Hole) // TI PROC194A RF_Via matrix, track and arc to GND via only
Clearance PROC194A_RF_Coplanar_Gap [OnLayer('Top Layer') AND (IsTrack OR IsArc) AND (InNet('TI_TX1') OR InNet('TI_TX2') OR InNet('TI_TX3') OR InNet('TI_TX4') OR InNet('TI_RX1') OR InNet('TI_RX2') OR InNet('TI_RX3') OR InNet('TI_RX4')) vs InNamedPolygon('GND_COPLANAR_FEED_REFERENCE')] p2: gap=10 ignorepadtopadclearanceinfootprint=FALSE except(3.78: Track-Poly; 3.94: Arc-Poly) // TI PROC194A clearances, feed tracks and arcs to named coplanar ground
Clearance Hybrid_35um_Polygon_Clearance [InPolygon] p3: gap=7.87 ignorepadtopadclearanceinfootprint=FALSE
Clearance [All] p4: gap=5.91 ignorepadtopadclearanceinfootprint=FALSE
DiffPairsRouting [All] p1: maxlimit=10 minlimit=10 mostfreqgap=10 toplayer_minwidth=15 toplayer_maxwidth=15 toplayer_prefwidth=15 midlayer2_minwidth=15 midlayer2_maxwidth=15 midlayer2_prefwidth=15 midlayer3_minwidth=15 midlayer3_maxwidth=15 midlayer3_prefwidth=15 midlayer5_minwidth=15 midlayer5_maxwidth=15 midlayer5_prefwidth=15 midlayer6_minwidth=15 midlayer6_maxwidth=15 midlayer6_prefwidth=15 midlayer7_minwidth=15 midlayer7_maxwidth=15 midlayer7_prefwidth=15 midlayer8_minwidth=15 midlayer8_maxwidth=15 midlayer8_prefwidth=15 bottomlayer_minwidth=15 bottomlayer_maxwidth=15 bottomlayer_prefwidth=15 substack1={9319A519-0D26-40B3-8AF8-C4998BECF1C7} toplayer_{9319a519-0d26-40b3-8af8-c4998becf1c7}_minwidth=15 toplayer_{9319a519-0d26-40b3-8af8-c4998becf1c7}_maxwidth=15 toplayer_{9319a519-0d26-40b3-8af8-c4998becf1c7}_prefwidth=15 midlayer2_{9319a519-0d26-40b3-8af8-c4998becf1c7}_minwidth=15 midlayer2_{9319a519-0d26-40b3-8af8-c4998becf1c7}_maxwidth=15 midlayer2_{9319a519-0d26-40b3-8af8-c4998becf1c7}_prefwidth=15 midlayer3_{9319a519-0d26-40b3-8af8-c4998becf1c7}_minwidth=15 midlayer3_{9319a519-0d26-40b3-8af8-c4998becf1c7}_maxwidth=15 midlayer3_{9319a519-0d26-40b3-8af8-c4998becf1c7}_prefwidth=15 midlayer5_{9319a519-0d26-40b3-8af8-c4998becf1c7}_minwidth=15 midlayer5_{9319a519-0d26-40b3-8af8-c4998becf1c7}_maxwidth=15 midlayer5_{9319a519-0d26-40b3-8af8-c4998becf1c7}_prefwidth=15 midlayer6_{9319a519-0d26-40b3-8af8-c4998becf1c7}_minwidth=15 midlayer6_{9319a519-0d26-40b3-8af8-c4998becf1c7}_maxwidth=15 midlayer6_{9319a519-0d26-40b3-8af8-c4998becf1c7}_prefwidth=15 midlayer7_{9319a519-0d26-40b3-8af8-c4998becf1c7}_minwidth=15 midlayer7_{9319a519-0d26-40b3-8af8-c4998becf1c7}_maxwidth=15 midlayer7_{9319a519-0d26-40b3-8af8-c4998becf1c7}_prefwidth=15 midlayer8_{9319a519-0d26-40b3-8af8-c4998becf1c7}_minwidth=15 midlayer8_{9319a519-0d26-40b3-8af8-c4998becf1c7}_maxwidth=15 midlayer8_{9319a519-0d26-40b3-8af8-c4998becf1c7}_prefwidth=15 bottomlayer_{9319a519-0d26-40b3-8af8-c4998becf1c7}_minwidth=15 bottomlayer_{9319a519-0d26-40b3-8af8-c4998becf1c7}_maxwidth=15 bottomlayer_{9319a519-0d26-40b3-8af8-c4998becf1c7}_prefwidth=15 maxuncoupledlength=500
HoleSize Connector_Mounting_NPTH [IsPad AND AsMils(Hole) > 100] p1: absolutevalues=TRUE maxlimit=120.08 minlimit=116.14 maxpercent=80.000 minpercent=20.000
HoleSize [All] p2: absolutevalues=TRUE maxlimit=100 minlimit=1 maxpercent=80.000 minpercent=20.000
HoleToHoleClearance [All] p1: gap=7.87 allowstackedmicrovias=TRUE
MinimumSolderMaskSliver [All] p1: minsoldermaskwidth=3.94
PolygonConnect GND_Vias_Direct_Return [IsVia AND InNet('GND')] p1: connectstyle=Direct reliefconductorwidth=10 reliefentries=4 polygonreliefangle="90 Angle" airgapwidth=10 // Solid connection of GND vias to reference and return polygons
PolygonConnect Bottom_GND_SMD_Thermal [IsPad AND OnLayer('Bottom Layer') AND InNet('GND') vs OnLayer('Bottom Layer')] p2: connectstyle=Relief reliefconductorwidth=6.69 reliefentries=4 polygonreliefangle="90 Angle" airgapwidth=7.87 // Bottom SMT ground thermal spokes
PolygonConnect Top_Digital_GND_SMD_Thermal [IsPad AND OnLayer('Top Layer') AND InNet('GND') vs IsNamedPolygon('GND_TOP_DIGITAL_RETURN')] p3: connectstyle=Relief reliefconductorwidth=6.69 reliefentries=4 polygonreliefangle="90 Angle" airgapwidth=7.87 // Top SMT ground thermal spokes outside RF feed and power switching zones
PolygonConnect [All] p4: connectstyle=Relief reliefconductorwidth=10 reliefentries=4 polygonreliefangle="90 Angle" airgapwidth=10
RoutingVias [All] p1: holewidth=9.84 width=19.68 viastyle="Through Hole" minholewidth=7.87 minwidth=15.75 maxholewidth=11.81 maxwidth=23.62
SilkToSilkClearance [All] p1: silktosilkclearance=3
SilkToSolderMaskClearance [IsPad] p1: minsilkscreentomaskgap=3 clearancetoexposedcopper=TRUE
SolderMaskExpansion [All] p1: expansion=0.98 istentingtop=FALSE
Width [All] p1: maxlimit=157.48 minlimit=5.91 preferedwidth=7.09 substack1={9319A519-0D26-40B3-8AF8-C4998BECF1C7}
24 further rules are at their usual default settings.

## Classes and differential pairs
net class EVT_CONTROL_COMPLETION: TI_FB_B1 TI_FB_B2 TI_FB_B3 TI_NERR_MCU TI_NetC14_1 TI_NetC123_2 TI_NetR29_1 TI_NetR63_1 TI_NetR186_1 TI_NetR190_2 TI_NRSTOUT TI_PMIC_EN TI_PMIC_NINT TI_SYNCCLKIN

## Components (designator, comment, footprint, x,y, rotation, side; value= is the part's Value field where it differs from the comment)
C1 "Comment" C_1206_3216Metric#1 2696.85,1299.21 r180 bottom
C2 "Comment" C_1206_3216Metric#1 2933.07,1338.58 r0 bottom
C3 "Comment" C_0603_1608Metric#1 2854.33,1220.47 r270 bottom
C4 "Comment" C_0603_1608Metric#1 2559.06,1299.21 r270 bottom
C6D "Comment" C_0603_1608Metric#1 1287.4,1897.64 r90 bottom
C6I "Comment" C_0603_1608Metric#1 1200.79,1862.2 r0 bottom
C7D "Comment" C_0603_1608Metric#1 1732.28,1653.54 r270 bottom
C10 "Comment" C_0603_1608Metric#1 1240.16,2519.68 r180 bottom
C11 "Comment" C_0603_1608Metric#1 2116.14,2952.76 r180 bottom
C12 "Comment" C_0805_2012Metric 2440.94,2381.89 r90 bottom
C13 "Comment" C_0402_1005Metric#1 1259.84,2185.04 r270 bottom
C14 "Comment" C_0603_1608Metric#1 1259.84,2086.61 r90 bottom
C15 "Comment" C_0402_1005Metric#1 2992.13,2421.26 r270 bottom
C20 "Comment" C_0402_1005Metric#1 3011.81,2263.78 r0 bottom
C21 "Comment" C_0603_1608Metric#1 2559.06,2165.35 r270 bottom
C22 "Comment" C_0402_1005Metric#1 3031.5,2342.52 r0 bottom
C40 "Comment" C_0402_1005Metric#2 2480.32,1318.9 r270 bottom
C90 "Comment" C_1206_3216Metric#2 1259.84,2381.89 r0 bottom
C91 "Comment" C_1206_3216Metric#3 1988.19,3051.18 r90 bottom
C92 "Comment" C_0603_1608Metric#2 2007.87,3169.29 r90 bottom
C93 "Comment" C_0603_1608Metric#2 826.77,2342.52 r180 bottom
C100 "Comment" C_0402_1005Metric#1 2913.39,2440.94 r90 bottom
C101 "Comment" C_0402_1005Metric#1 1299.21,2972.44 r180 bottom
C102 "Comment" C_0402_1005Metric#1 2913.39,2519.68 r180 bottom
C103 "Comment" C_0402_1005Metric#1 2755.91,2500 r180 bottom
C104 "Comment" C_0402_1005Metric#1 2834.65,2440.94 r90 bottom
C105 "Comment" C_0402_1005Metric#1 2303.15,1496.06 r0 bottom
C106 "Comment" C_0402_1005Metric#1 2854.33,2342.52 r270 bottom
C107 "Comment" C_0402_1005Metric#2 2303.15,1417.32 r0 bottom
C108 "Comment" C_0402_1005Metric#1 2775.59,2342.52 r0 bottom
C109 "Comment" C_0402_1005Metric#1 2913.39,2263.78 r0 bottom
C110 "Comment" C_0402_1005Metric#1 2933.07,2342.52 r0 bottom
C111 "Comment" C_0402_1005Metric#1 2913.39,2598.43 r90 bottom
C112 "Comment" C_0402_1005Metric#1 2185.04,1338.58 r180 bottom
C113 "Comment" C_0402_1005Metric#1 2913.39,2677.17 r180 bottom
C114 "Comment" C_0402_1005Metric#1 2755.91,2421.26 r180 bottom
C115 "Comment" C_0402_1005Metric#1 2283.46,1338.58 r180 bottom
C800 "Comment" C_1210_3225Metric 1066.93,2913.39 r180 bottom
C801 "Comment" C_1210_3225Metric 1086.61,3051.18 r180 bottom
C802 "Comment" C_0603_1608Metric#1 1181.1,2814.96 r90 bottom
C803 "Comment" C_0603_1608Metric#1 960.63,2578.74 r90 bottom
C804 "Comment" C_0603_1608Metric#1 875.98,2555.12 r0 bottom
C805 "Comment" C_0603_1608Metric#1 1135.83,2519.68 r0 bottom
C806 "Comment" C_1210_3225Metric 1037.4,2125.98 r270 bottom
C807 "Comment" C_1210_3225Metric 1151.57,2102.36 r90 bottom
C808 "Comment" C_1210_3225Metric 771.65,2472.44 r0 bottom
C809 "Comment" C_1210_3225Metric 653.54,2090.55 r90 bottom
C_CAN_RAD "Comment" C_0402_1005Metric#2 2431.1,1181.1 r0 bottom
C_FRAME "Comment" C_0402_1005Metric#2 2185.04,1702.76 r90 bottom
C_USB_1U "Comment" C_0603_1608Metric#1 2696.85,1062.99 r90 bottom
C_USB_4U7 "Comment" C_0603_1608Metric#1 2598.43,925.2 r180 bottom
C_USB_100N "Comment" C_0402_1005Metric#2 2618.11,846.46 r0 bottom
D1 "Comment" D_SMC 905.51,1998.03 r90 bottom
D3 "Comment" USON-10_2.5x1.0mm_P0.5mm 2598.43,2047.24 r90 bottom
D4 "Comment" SOT-23 2598.43,1909.45 r90 bottom
D8 "Comment" USON-10_2.5x1.0mm_P0.5mm 2657.48,2480.32 r270 bottom
D_USB "Comment" USON-10_2.5x1.0mm_P0.5mm 2401.57,944.88 r180 bottom
FB1 "Comment" L_0603_1608Metric 1220.47,1988.19 r180 bottom
J1 "Comment" Molex_43650-0200_RA_THT_2P 1161.42,1771.65 r270 bottom
J6 "Comment" Molex_43045-0600_RA_THT_6P 2834.65,1850.39 r90 bottom
J8 "Comment" JST_GH_SM06B-GHS-TB_1x06-1MP_P1.25mm_Horizontal 2637.8,2696.85 r270 bottom
J10 "Comment" TagConnect_TC2030_NL 1870.08,3051.18 r270 bottom
JUSB1 "Comment" CONN_105017-0001 2716.54,2992.13 r0 bottom
L1 "Comment" Coilcraft_XFL4020_4x4 2933.07,1496.06 r270 bottom
L8 "Comment" L_Coilcraft_XAL7070-XXX 1062.99,2352.36 r270 bottom
L9 "Comment" Coilcraft_XFL4020_4x4 1692.91,3031.5 r270 bottom
Q6 "Comment" VSON-8_3.3x3.3mm_P0.65mm_NexFET 1066.93,1511.81 r0 bottom
Q7 "Comment" SOT-23 866.14,1496.06 r270 bottom
R1 "Comment" R_0603_1608Metric#1 1472.44,1826.77 r0 bottom
R2 "Comment" R_0603_1608Metric#1 2204.72,1496.06 r0 bottom
R5P "Comment" R_0603_1608Metric#2 2992.13,1633.86 r0 bottom
R6F "Comment" R_0603_1608Metric#2 2283.46,1771.65 r90 bottom
R7F "Comment" R_0603_1608Metric#2 2440.94,1889.76 r90 bottom
R10 "Comment" R_0603_1608Metric#1 2598.43,2362.2 r90 bottom
R40 "Comment" R_0603_1608Metric#2 3090.55,1633.86 r270 bottom
R41 "Comment" R_0603_1608Metric#1 2874.02,1633.86 r0 bottom
R42 "Comment" R_0603_1608Metric#3 3070.87,1496.06 r0 bottom
R61 "Comment" R_0603_1608Metric#2 1092.52,1901.57 r0 bottom
R62 "Comment" R_0603_1608Metric#2 1210.63,1915.35 r0 bottom
R63 "Comment" R_0603_1608Metric#1 1013.78,1860.24 r270 bottom
R70 "Comment" R_0603_1608Metric#2 2440.94,2086.61 r90 bottom
R71 "Comment" R_0603_1608Metric#4 1929.13,1318.9 r180 bottom
R72 "Comment" R_0603_1608Metric#4 2047.24,1318.9 r180 bottom
R73 "Comment" R_0603_1608Metric#1 1929.13,1240.16 r180 bottom
R90 "Comment" R_0603_1608Metric#3 1377.95,2992.13 r180 bottom
R600 "Comment" R_0603_1608Metric#2 2598.43,2263.78 r180 bottom
R601 "Comment" R_0402_1005Metric#1 2716.54,2263.78 r180 bottom
R602 "Comment" R_0402_1005Metric#2 2814.96,2263.78 r180 bottom
R603 "Comment" R_0402_1005Metric#2 2440.94,2500 r90 bottom
R604 "Comment" R_0402_1005Metric#3 2696.85,2342.52 r90 bottom
R605 "Comment" R_0603_1608Metric#3 2519.68,2421.26 r180 bottom
R800 "Comment" R_0603_1608Metric#1 944.88,2659.45 r180 bottom
R801 "Comment" R_0603_1608Metric#1 944.88,2724.41 r180 bottom
R802 "Comment" R_0603_1608Metric#1 875.98,2604.33 r0 bottom
R803 "Comment" R_0603_1608Metric#1 954.72,2805.12 r90 bottom
R804 "Comment" R_0603_1608Metric#1 1472.44,1649.61 r0 bottom
R805 "Comment" R_0603_1608Metric#1 1496.06,1582.68 r0 bottom
R806 "Comment" R_0603_1608Metric#1 1484.25,1732.28 r0 bottom
R_CAN_SHDN "Comment" R_0603_1608Metric#3 2381.89,1309.06 r90 bottom
R_CAN_STB "Comment" R_0603_1608Metric#1 2401.57,1072.83 r180 bottom
R_CAN_TERM "Comment" R_0603_1608Metric#2 2194.88,1151.57 r270 bottom
R_FRAME_PD "Comment" R_0603_1608Metric#1 2047.24,1781.5 r270 bottom
R_USB_CTS "Comment" R_0402_1005Metric#1 2578.74,1200.79 r180 bottom
R_USB_RESET "Comment" R_0402_1005Metric#1 2657.48,1200.79 r90 bottom
R_USB_VBUS_H "Comment" R_0402_1005Metric#1 2696.85,944.88 r90 bottom
R_USB_VBUS_L "Comment" R_0402_1005Metric#1 2736.22,1161.42 r180 bottom
R_USB_WAKE "Comment" R_0402_1005Metric#1 2775.59,1062.99 r90 bottom
RAD_C1 "Comment" 0603L 915.35,1427.17 r270 top
RAD_C2 "Comment" 0402L 1250,1377.95 r90 top
RAD_C3 "Comment" 0603L 2500,1289.37 r180 top
RAD_C5 "Comment" 0402L 1082.68,1161.42 r90 top
RAD_C6 "Comment" FP-GCJ188C70J475KE02J_0603-MFG 2263.78,905.51 r0 top
RAD_C8 "Comment" FP-GCJ188C70J475KE02J_0603-MFG 2086.61,885.83 r90 top
RAD_C9 "Comment" FP-NFM18HC105C1C3D_0603-MFG 1830.71,1062.99 r90 top
RAD_C10 "Comment" 0603L 803.56,1632.96 r270 top
RAD_C14 "Comment" 0402L 1181.1,1840.55 r180 top
RAD_C15 "Comment" 0805L 1870.08,1181.1 r90 top
RAD_C17 "Comment" 0402L 1692.91,748.03 r270 bottom
RAD_C19 "Comment" 0402L 1535.43,688.98 r0 top
RAD_C21 "Comment" 0402L 738.19,1671.39 r180 top
RAD_C22 "Comment" 0402L 565.97,1921.91 r180 top
RAD_C23 "Comment" 1206_180L 560.97,1861.12 r0 bottom
RAD_C25 "Comment" 1206_180L 560.97,1861.12 r0 top
RAD_C26 "Comment" 1206_180L 560.97,1772.02 r0 bottom
RAD_C29 "Comment" 1206_180L 560.97,1772.02 r0 top
RAD_C31 "Comment" 0805L 2381.89,807.09 r90 top
RAD_C58 "Comment" FP-NFM18HC105C1C3D_0603-MFG 1929.13,787.4 r180 bottom
RAD_C60 "Comment" 0603L 728.35,2224.41 r90 bottom
RAD_C81 "Comment" 0402L 1791.34,787.4 r180 top
RAD_C92 "Comment" 0402L 1161.42,984.25 r270 bottom
RAD_C96 "Comment" 0402L 1377.95,846.46 r90 top
RAD_C99 "Comment" SM_RADIAL_6.3BMM 1259.84,2874.02 r90 top
RAD_C100 "Comment" 1206_180L 807.09,2303.15 r180 top
RAD_C101 "Comment" 1206_180L 807.09,1909.45 r180 top
RAD_C102 "Comment" FP-GRT155R70J105KE01D_0402-MFG 1617.55,1441.52 r0 bottom
RAD_C103 "Comment" FP-GRT155R70J105KE01D_0402-MFG 1519.69,1377.95 r270 bottom
RAD_C104 "Comment" 0603L 748.03,2224.41 r0 top
RAD_C105 "Comment" 0402L 1437.01,787.4 r180 bottom
RAD_C106 "Comment" FP-GCM1555C1H3R9BA16D_0402-MFG 1763.72,1604.37 r0 top
RAD_C107 "Comment" 0402L 1437.01,925.2 r180 top
RAD_C108 "Comment" FP-GCM1555C1H3R9BA16D_0402-MFG 1860.95,1604.58 r180 top
RAD_C110 "Comment" 0805L 1535.43,1003.94 r180 top
RAD_C111 "Comment" 0402L 1299.21,1003.94 r90 top
RAD_C112 "Comment" 0805L 1240.16,1161.42 r90 top
RAD_C113 "Comment" 0402L 1377.95,866.14 r90 bottom
RAD_C114 "Comment" 0805L 1673.23,1003.94 r180 top
RAD_C115 "Comment" 0402L 1220.47,1062.99 r0 top
RAD_C116 "Comment" 0805L 1397.64,1003.94 r180 top
RAD_C117 "Comment" 0402L 1161.42,1161.42 r270 top
RAD_C118 "Comment" FP-CGA4J1X7R1H475K125AC_0805-MFG 657.35,1927.05 r0 top
RAD_C119 "Comment" 0805L 2007.87,767.72 r180 top
RAD_C123 "Comment" 0603L 2047.24,1220.47 r180 top
RAD_C124 "Comment" FP-GCJ188C70J475KE02J_0603-MFG 2165.35,1220.47 r0 top
RAD_C125 "Comment" 0805_155 1948.82,1181.1 r90 top
RAD_C126 "Comment" 0603L 1200.79,1968.5 r270 top
RAD_C129 "Comment" 0805_155 1988.19,846.46 r0 top
RAD_C130 "Comment" 0805_155 1948.82,1023.62 r270 bottom
RAD_C132 "Comment" 0805_155 2145.67,940.94 r90 bottom
RAD_C134 "Comment" 0805_155 1909.45,1043.31 r90 top
RAD_C137 "Comment" 0603L 1594.49,944.88 r0 bottom
RAD_C138 "Comment" 0402L 1240.16,944.88 r180 bottom
RAD_C139 "Comment" 0402L 1279.53,1673.23 r0 top
RAD_C140 "Comment" 0402L 1299.21,866.14 r180 bottom
RAD_C141 "Comment" 0402L 1181.1,1082.68 r270 bottom
RAD_C142 "Comment" 0402L 1358.27,1673.23 r270 top
RAD_C143 "Comment" 0805_155 2362.2,944.88 r270 top
RAD_C144 "Comment" FP-GCJ188C70J475KE02J_0603-MFG 2047.24,1240.16 r0 bottom
RAD_C145 "Comment" 0603L 2677.17,1200.79 r90 top
RAD_C146 "Comment" 0603L 1535.43,925.2 r180 top
RAD_C149 "Comment" 0603L 2618.11,1102.36 r0 top
RAD_C150 "Comment" 0402L 1365.58,1467.11 r180 bottom
RAD_C153 "Comment" FP-GCJ188C70J475KE02J_0603-MFG 2263.78,748.03 r0 top
RAD_C163 "Comment" 0402L 1614.17,846.46 r90 top
RAD_C164 "Comment" 0402L 1535.43,866.14 r0 bottom
RAD_C165 "Comment" 0402L 1338.58,925.2 r180 top
RAD_C168 "Comment" 0402L 1456.69,846.46 r90 top
RAD_C170 "Comment" 0402L 1614.17,866.14 r270 bottom
RAD_C172 "Comment" 0402L 1456.69,866.14 r270 bottom
RAD_C173 "Comment" FP-CGA4J1X7R1H475K125AC_0805-MFG 866.14,2125.98 r270 top
RAD_C174 "Comment" 0402L 1141.73,1062.99 r90 top
RAD_C175 "Comment" 0402L 1712.6,866.14 r90 top
RAD_C176 "Comment" 0402L 1220.47,984.25 r270 top
RAD_C177 "Comment" 0402L 1102.36,1082.68 r90 bottom
RAD_C179 "Comment" FP-NFM18HC105C1C3D_0603-MFG 1677.17,1445.87 r90 bottom
RAD_C180 "Comment" 0402L 1544.71,1441.52 r0 bottom
RAD_C181 "Comment" FP-NFM18HC105C1C3D_0603-MFG 1692.91,925.2 r270 bottom
RAD_C195 "Comment" 0603L 690.2,1828.57 r270 top
RAD_C199 "Comment" 0402L 2460.63,767.72 r270 bottom
RAD_C200 "Comment" 0402L 2165.35,708.66 r180 top
RAD_C201 "Comment" 0805_155 2283.46,826.77 r0 top
RAD_C202 "Comment" 0805_155 2145.67,787.4 r0 top
RAD_L1 "Comment" TFM201610ALMA 2007.87,1062.99 r270 top
RAD_L2 "Comment" "FP-TFM201610ALMAR24MTAA_0806 (2016 Metric)-MFG" 2322.83,1062.99 r270 top
RAD_L5 "Comment" FP-XAL4030-472MEC_SMD2-MFG 1023.62,2480.32 r180 top
RAD_L6 "Comment" FP-XEL4030-222MEC_SMT2_4MM0_4MM0-MFG 596.06,1659.68 r180 top
RAD_L8 "Comment" "FP-TFM201610ALMAR24MTAA_0806 (2016 Metric)-MFG" 2165.35,885.83 r90 top
RAD_L9 "Comment" "FP-TFM201610ALMAR24MTAA_0806 (2016 Metric)-MFG" 2007.87,944.88 r90 top
RAD_NT1 "Comment" Net-Tie_50milWide_30milLong 2500,925.2 r90 bottom net-tie
RAD_NT2 "Comment" Net-Tie_50milWide_30milLong 2500,1200.79 r90 bottom net-tie
RAD_NT3 "Comment" Net-Tie_50milWide_30milLong 2149.61,1006.65 r270 bottom net-tie
RAD_NT4 "Comment" Net-Tie_50milWide_30milLong 2381.89,767.72 r0 bottom net-tie
RAD_P1 "Comment" VPP_SERVICE_SMT_D1p5_P2p5 1850.39,3011.81 r0 top
RAD_R1 "Comment" 0402L 1122.05,1948.82 r180 top
RAD_R2 "Comment" 0402L 807.09,2244.09 r180 bottom
RAD_R7 "Comment" 0402L 748.03,2125.98 r180 bottom
RAD_R9 "Comment" 0402L 748.03,2047.24 r180 bottom
RAD_R13 "Comment" 0402L 1771.65,964.57 r90 top
RAD_R14 "Comment" 0402L 1811.02,866.14 r0 top
RAD_R17 "Comment" 0402L 2066.93,688.98 r180 top
RAD_R26 "Comment" 0402L 1102.36,1673.23 r270 top
RAD_R27 "Comment" 0402L 1692.91,708.66 r0 top
RAD_R29 "Comment" 0402L 925.2,1240.16 r0 top
RAD_R30 "Comment" 1206L 1043.31,944.88 r90 top
RAD_R32 "Comment" 0402L 1535.43,708.66 r0 bottom
RAD_R33 "Comment" 0402L 1614.17,688.98 r90 top
RAD_R35 "Comment" 0402L 1456.69,688.98 r90 top
RAD_R37 "Comment" 0402L 1250,1476.38 r270 top
RAD_R38 "Comment" 0402L 1102.36,1594.49 r180 top
RAD_R39 "Comment" FP-ERJ-1GNF33R2C_0201-MFG 1072.83,1240.16 r90 top
RAD_R40 "Comment" FP-ERJ-1GNF33R2C_0201-MFG 1023.62,1594.49 r90 top
RAD_R41 "Comment" 0402L 1151.57,1240.16 r180 top
RAD_R42 "Comment" FP-ERJ-1GNF33R2C_0201-MFG 915.35,1515.75 r90 top
RAD_R43 "Comment" 0402L 1250,1279.53 r270 top
RAD_R44 "Comment" FP-ERJ-1GNF33R2C_0201-MFG 1003.94,1240.16 r90 top
RAD_R45 "Comment" FP-ERJ-1GNF33R2C_0201-MFG 1334.08,1262.39 r0 bottom
RAD_R47 "Comment" 0402L 1771.65,708.66 r180 bottom
RAD_R49 "Comment" 0402L 1250,1564.96 r270 top
RAD_R56 "Comment" 0402L 984.25,1082.68 r270 top
RAD_R57 "Comment" 0402L 1161.42,807.09 r0 top
RAD_R58 "Comment" 0402L 1062.99,925.2 r90 bottom
RAD_R59 "Comment" 0402L 1259.84,1830.71 r180 top
RAD_R60 "Comment" 1206L 1397.64,708.66 r180 bottom
RAD_R62 "Comment" 0402L 1614.17,669.29 r270 bottom
RAD_R63 "Comment" 0402L 2381.89,688.98 r0 bottom
RAD_R64 "Comment" 1206L 1299.21,748.03 r0 top
RAD_R65 "Comment" 0402L 1072.83,1811.02 r0 top
RAD_R66 "Comment" 0402L 1141.73,826.77 r270 bottom
RAD_R71 "Comment" 0402L 1948.82,708.66 r90 bottom
RAD_R73 "Comment" FP-HCJ0603ZT0R00_0603-MFG 2421.26,846.46 r180 bottom
RAD_R75 "Comment" 0402L 2244.09,669.29 r270 top
RAD_R76 "Comment" 0402L 2539.37,846.46 r0 bottom
RAD_R99 "Comment" 0402L 2519.68,984.25 r180 top
RAD_R104 "Comment" FP-HCJ0603ZT0R00_0603-MFG 2533.46,926.18 r180 top
RAD_R106 "Comment" 0402L 1889.76,767.72 r0 top
RAD_R111 "Comment" FP-HCJ0603ZT0R00_0603-MFG 1889.76,944.88 r0 top
RAD_R116 "Comment" 0402L 2460.63,826.77 r270 top
RAD_R125 "Comment" 0402L 2362.2,708.66 r0 top
RAD_R128 "Comment" 0402L 1744.09,1665.35 r270 top
RAD_R129 "Comment" 0402L 1003.94,1161.42 r180 top
RAD_R186 "Comment" 0402L 2070.87,653.54 r180 top
RAD_R190 "Comment" 0402L 2519.68,1062.99 r180 top
RAD_R193 "Comment" 0402L 1830.71,787.4 r180 bottom
RAD_R200 "Comment" FP-HCJ0603ZT0R00_0603-MFG 1870.08,905.51 r270 bottom
RAD_R218 "Comment" 0201L 1614.17,767.72 r270 top
RAD_R264 "Comment" 0402L 1535.43,767.72 r0 top
RAD_R276 "Comment" 0402L 1200.79,2263.78 r270 top
RAD_R277 "Comment" 0402L 748.03,1968.5 r0 bottom
RAD_R291 "Comment" 0402L 1791.34,866.14 r270 bottom
RAD_R292 "Comment" 0402L 2322.83,1574.8 r270 bottom
RAD_R299 "Comment" 0402L 1062.99,1082.68 r180 top
RAD_R300 "Comment" 0402L 1692.91,787.4 r0 top
RAD_R301 "Comment" 0402L 1338.58,787.4 r180 bottom
RAD_R302 "Comment" 0402L 1220.47,866.14 r90 bottom
RAD_R305 "Comment" 0402L 1614.17,767.72 r90 bottom
RAD_R307 "Comment" 0402L 1299.21,826.77 r180 top
RAD_R309 "Comment" 0402L 1723.43,1154.53 r0 bottom
RAD_R310 "Comment" 0402L 1082.68,1003.94 r0 bottom
RAD_R311 "Comment" 0402L 1181.1,885.83 r0 top
RAD_R313 "Comment" 0402L 1023.62,1122.05 r0 bottom
RAD_R346 "Comment" 1206L 925.2,1220.47 r90 bottom
RAD_R348 "Comment" 0402L 1003.94,1043.31 r90 bottom
RAD_R352 "Comment" 0402L 1240.16,787.4 r180 bottom
RAD_R386 "Comment" 0402L 1141.73,905.51 r180 bottom
RAD_R409 "Comment" 0402L 2598.43,1023.62 r90 top
RAD_TP8 "Comment" TP_25MIL-SMT 1988.19,688.98 r270 top
RAD_U1 "Comment" FP-GD25B64CWAG_WSON8-IPC_C 1082.68,1417.32 r270 top
RAD_U2 "Comment" DRR0012E-MFG 787.4,1791.34 r90 top
RAD_U8 "Comment" RXV0028A-MFG 2165.35,1062.99 r0 top
RAD_U9 "Comment" DGS0010A_L 2421.26,1141.73 r90 top
RAD_U11 "Comment" DGS0010A_L 1988.19,1614.17 r0 bottom
RAD_U12 "Comment" DGS0010A_L 2716.54,1377.95 r270 top
RAD_U22 "Comment" DGS0010A_L 2027.56,1141.73 r180 bottom
RAD_U27 "Comment" DBV0005A-MFG 2559.06,1200.79 r0 top
RAD_U29 "Comment" ALT0266A-MFG 1537.82,1300.78 r270 top
RAD_Y3 "Comment" FP-NX2016SA-50M-STD-CZS-3_SMT4_2MM0_1MM6-MFG 1832.69,1697.35 r0 top
SW1 "Comment" ESwitch_TL3301_GullWing_6x6 2500,1594.49 r180 bottom
TP1 "Comment" TestPoint_Pad_D1.0mm 2992.13,2500 r270 bottom
TP2 "Comment" TestPoint_Pad_D1.0mm 2992.13,2578.74 r180 bottom
TP_RAD_FLASH "Comment" TestPoint_Pad_D1.5mm 1535.43,787.4 r180 bottom
TP_RAD_GND "Comment" TestPoint_Pad_D1.5mm 1023.62,1200.79 r180 bottom
TP_RAD_RESET "Comment" TestPoint_Pad_D1.5mm 2661.42,795.28 r0 top
TP_RAD_VIO "Comment" TestPoint_Pad_D1.5mm 1141.73,964.57 r0 top
U1 "Comment" LQFP-176_24x24mm_P0.5mm 1850.39,2381.89 r90 bottom
U2 "Comment" ICM-42688-P_LGA14_2.5x3mm_P0.5mm 2460.63,2224.41 r0 bottom
U4 "Comment" Texas_DRB0008A 2736.22,1614.17 r90 bottom
U5 "Comment" VQFN-16-1EP_3x3mm_P0.5mm_EP1.68x1.68mm#1 2736.22,1437.01 r270 bottom
U6 "Comment" Texas_RGE0024C_VQFN-24-1EP_4x4mm_P0.5mm_EP2.1x2.1mm 1318.9,1732.28 r0 bottom
U7 "Comment" TPS259470A_RPW0010A_VQFN-HR-10_2x2mm_P0.475mm 1791.34,1771.65 r180 bottom
U8 "Comment" Texas_RNP0030B_WQFN-30-1EP_4x6mm_P0.5mm_EP1.8x4.5mm_ThermalVias 1141.73,2657.48 r90 bottom
U9 "Comment" VQFN-16-1EP_3x3mm_P0.5mm_EP1.68x1.68mm#2 1496.06,3011.81 r180 bottom
U_CAN_RAD "Comment" Texas_DRB0008A 2312.99,1190.94 r90 bottom
U_FRAME "Comment" DCK0005A_N 2175.2,1781.5 r180 bottom
U_USB "Comment" CP2102N_QFN20_3x3_EP_Rev1p5 2559.06,1062.99 r180 bottom
Y1 "Comment" Oscillator_SMD_ECS_2520MV-xxx-xx-4Pin_2.5x2.0mm 1673.23,1771.65 r180 bottom

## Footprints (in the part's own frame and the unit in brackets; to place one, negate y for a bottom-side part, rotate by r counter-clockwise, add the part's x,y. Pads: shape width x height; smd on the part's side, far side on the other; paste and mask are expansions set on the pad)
0201L [mm] "Data from Kemet datasheet CC101_COM dated 7/28/11"
  rect 0.36x0.32 smd mask+0.048: 1(-0.28,0) 2(0.28,0)
  silkscreen extent -0.68,-0.68 0.68,0.68
0402L [mm] "0402 from SM-752 data"
  rect 0.6x0.5 smd: 1(-0.5,0) 2(0.5,0)
  silkscreen extent -0.88,-0.68 0.88,0.68
0603L [mm] "0603 from SM-752 data"
  rect 0.8x0.85 smd: 1(-0.7,0) 2(0.7,0)
  silkscreen extent -1.18,-0.68 1.18,0.68
0805_155 [mm] "SMD, 2-Leads, Body 2x1.25mm"
  rrect12% 0.825x1.55 smd: 1(-0.875,0) 2(0.875,0)
  silkscreen extent -0.35,0.85 0.35,0.85
0805L [mm] "0805 from SM-752 data"
  rect 1.1x1.4 smd: 1(-0.75,0) 2(0.75,0)
1206_180L [mm] "1206_180"
  rect 1.1x1.75 smd: 1(-1.35,0) 2(1.35,0)
1206L [mm] "1206 from SM-752 data"
  rect 1.1x1.75 smd: 1(-1.35,0) 2(1.35,0)
  silkscreen extent -0.64,-0.95 0.64,0.95
ALT0266A-MFG [mm]
  round 0.35 smd paste+0 mask+0.07: A1(-5.525,5.525) A2(-4.875,5.525) A4(-3.575,5.525) A6(-2.275,5.525) A8(-0.975,5.525) A10(0.325,5.525) A11(0.975,5.525) A12(1.625,5.525) A13(2.275,5.525) A14(2.925,5.525) A15(3.575,5.525) A16(4.225,5.525) A17(4.875,5.525) A18(5.525,5.525) B1(-5.525,4.875) B2(-4.875,4.875) B3(-4.225,4.875) B4(-3.575,4.875) B5(-2.925,4.875) B6(-2.275,4.875) B7(-1.625,4.875) B8(-0.975,4.875) B9(-0.325,4.875) B10(0.325,4.875) B11(0.975,4.875) B12(1.625,4.875) B13(2.275,4.875) B14(2.925,4.875) B15(3.575,4.875) B16(4.225,4.875) B17(4.875,4.875) B18(5.525,4.875) C1(-5.525,4.225) C2(-4.875,4.225) C3(-4.225,4.225) C4(-3.575,4.225) C5(-2.925,4.225) C6(-2.275,4.225) C7(-1.625,4.225) C8(-0.975,4.225) C9(-0.325,4.225) C10(0.325,4.225) C11(0.975,4.225) C12(1.625,4.225) C14(2.925,4.225) C16(4.225,4.225) C17(4.875,4.225) C18(5.525,4.225) D1(-5.525,3.575) D2(-4.875,3.575) D3(-4.225,3.575) D6(-2.275,3.575) D7(-1.625,3.575) D9(-0.325,3.575) D11(0.975,3.575) D13(2.275,3.575) D15(3.575,3.575) D16(4.225,3.575) D17(4.875,3.575) D18(5.525,3.575) E1(-5.525,2.925) E2(-4.875,2.925) E3(-4.225,2.925) E4(-3.575,2.925) E11(0.975,2.925) E12(1.625,2.925) E13(2.275,2.925) E14(2.925,2.925) E15(3.575,2.925) E17(4.875,2.925) E18(5.525,2.925) F2(-4.875,2.275) F3(-4.225,2.275) F6(-2.275,2.275) F7(-1.625,2.275) F8(-0.975,2.275) F9(-0.325,2.275) F10(0.325,2.275) F11(0.975,2.275) F12(1.625,2.275) F13(2.275,2.275) F14(2.925,2.275) F16(4.225,2.275) F17(4.875,2.275) F18(5.525,2.275) G1(-5.525,1.625) G2(-4.875,1.625) G3(-4.225,1.625) G4(-3.575,1.625) G6(-2.275,1.625) G7(-1.625,1.625) G8(-0.975,1.625) G9(-0.325,1.625) G10(0.325,1.625) G11(0.975,1.625) G12(1.625,1.625) G13(2.275,1.625) G14(2.925,1.625) G15(3.575,1.625) G17(4.875,1.625) G18(5.525,1.625) H2(-4.875,0.975) H3(-4.225,0.975) H4(-3.575,0.975) H6(-2.275,0.975) H7(-1.625,0.975) H8(-0.975,0.975) H9(-0.325,0.975) H10(0.325,0.975) H11(0.975,0.975) H12(1.625,0.975) H13(2.275,0.975) H14(2.925,0.975) H16(4.225,0.975) H17(4.875,0.975) H18(5.525,0.975) J1(-5.525,0.325) J2(-4.875,0.325) J3(-4.225,0.325) J6(-2.275,0.325) J7(-1.625,0.325) J8(-0.975,0.325) J9(-0.325,0.325) J10(0.325,0.325) J11(0.975,0.325) J12(1.625,0.325) J13(2.275,0.325) J14(2.925,0.325) J15(3.575,0.325) J17(4.875,0.325) J18(5.525,0.325) K2(-4.875,-0.325) K3(-4.225,-0.325) K4(-3.575,-0.325) K6(-2.275,-0.325) K7(-1.625,-0.325) K8(-0.975,-0.325) K9(-0.325,-0.325) K10(0.325,-0.325) K11(0.975,-0.325) K12(1.625,-0.325) K13(2.275,-0.325) K14(2.925,-0.325) K16(4.225,-0.325) K17(4.875,-0.325) K18(5.525,-0.325) L1(-5.525,-0.975) L2(-4.875,-0.975) L3(-4.225,-0.975) L6(-2.275,-0.975) L7(-1.625,-0.975) L8(-0.975,-0.975) L9(-0.325,-0.975) L10(0.325,-0.975) L11(0.975,-0.975) L12(1.625,-0.975) L13(2.275,-0.975) L14(2.925,-0.975) L15(3.575,-0.975) L17(4.875,-0.975) L18(5.525,-0.975) M2(-4.875,-1.625) M3(-4.225,-1.625) M4(-3.575,-1.625) M6(-2.275,-1.625) M7(-1.625,-1.625) M8(-0.975,-1.625) M9(-0.325,-1.625) M10(0.325,-1.625) M11(0.975,-1.625) M12(1.625,-1.625) M13(2.275,-1.625) M14(2.925,-1.625) M16(4.225,-1.625) M17(4.875,-1.625) M18(5.525,-1.625) N1(-5.525,-2.275) N2(-4.875,-2.275) N3(-4.225,-2.275) N6(-2.275,-2.275) N7(-1.625,-2.275) N8(-0.975,-2.275) N9(-0.325,-2.275) N10(0.325,-2.275) N11(0.975,-2.275) N12(1.625,-2.275) N13(2.275,-2.275) N14(2.925,-2.275) N15(3.575,-2.275) N17(4.875,-2.275) N18(5.525,-2.275) P1(-5.525,-2.925) P2(-4.875,-2.925) P3(-4.225,-2.925) P6(-2.275,-2.925) P7(-1.625,-2.925) P8(-0.975,-2.925) P9(-0.325,-2.925) P10(0.325,-2.925) P11(0.975,-2.925) P12(1.625,-2.925) P13(2.275,-2.925) P14(2.925,-2.925) P16(4.225,-2.925) P17(4.875,-2.925) P18(5.525,-2.925) R1(-5.525,-3.575) R2(-4.875,-3.575) R3(-4.225,-3.575) R4(-3.575,-3.575) R6(-2.275,-3.575) R8(-0.975,-3.575) R10(0.325,-3.575) R12(1.625,-3.575) R14(2.925,-3.575) R15(3.575,-3.575) R17(4.875,-3.575) R18(5.525,-3.575) T1(-5.525,-4.225) T2(-4.875,-4.225) T3(-4.225,-4.225) T5(-2.925,-4.225) T7(-1.625,-4.225) T9(-0.325,-4.225) T11(0.975,-4.225) T13(2.275,-4.225) T15(3.575,-4.225) T16(4.225,-4.225) T17(4.875,-4.225) T18(5.525,-4.225) U1(-5.525,-4.875) U2(-4.875,-4.875) U3(-4.225,-4.875) U4(-3.575,-4.875) U5(-2.925,-4.875) U6(-2.275,-4.875) U7(-1.625,-4.875) U8(-0.975,-4.875) U9(-0.325,-4.875) U10(0.325,-4.875) U11(0.975,-4.875) U12(1.625,-4.875) U13(2.275,-4.875) U14(2.925,-4.875) U15(3.575,-4.875) U16(4.225,-4.875) U17(4.875,-4.875) U18(5.525,-4.875) V1(-5.525,-5.525) V2(-4.875,-5.525) V3(-4.225,-5.525) V4(-3.575,-5.525) V5(-2.925,-5.525) V6(-2.275,-5.525) V7(-1.625,-5.525) V8(-0.975,-5.525) V9(-0.325,-5.525) V10(0.325,-5.525) V11(0.975,-5.525) V12(1.625,-5.525) V13(2.275,-5.525) V14(2.925,-5.525) V15(3.575,-5.525) V16(4.225,-5.525) V17(4.875,-5.525) V18(5.525,-5.525)
  silkscreen extent -6.08,-6.08 6.08,6.08
C_0402_1005Metric#1 [mm]
  rrect25% 0.56x0.62 smd: 1(-0.48,0)
  rrect50% 0.56x0.62 smd: 2(0.48,0)
  silkscreen extent -0.84,-0.68 0.84,0.68
C_0402_1005Metric#2 [mm]
  rrect50% 0.62x0.56 smd: 1(0,0.48) 2(0,-0.48)
  silkscreen extent -0.68,-0.84 0.68,0.84
C_0603_1608Metric#1 [mm]
  rrect25% 0.9x0.95 smd: 1(-0.775,0)
  rrect50% 0.9x0.95 smd: 2(0.775,0)
  silkscreen extent -1.31,-0.68 1.3,0.68
C_0603_1608Metric#2 [mm]
  rrect50% 0.95x0.9 smd: 1(0,-0.775) 2(0,0.775)
  silkscreen extent -0.68,-1.3 0.68,1.31
C_0805_2012Metric [mm]
  rrect25% 1x1.45 smd: 1(-0.95,0)
  rrect50% 1x1.45 smd: 2(0.95,0)
  silkscreen extent -0.38,-0.8 0.46,0.8
C_1206_3216Metric#1 [mm]
  rrect22% 1.15x1.8 smd: 1(-1.475,0)
  rrect50% 1.15x1.8 smd: 2(1.475,0)
  silkscreen extent -0.83,-0.98 0.94,0.98
C_1206_3216Metric#2 [mm]
  rrect50% 1.8x1.15 smd: 1(0,-1.475) 2(0,1.475)
  silkscreen extent -0.98,-0.94 0.98,0.94
C_1206_3216Metric#3 [mm]
  rrect50% 1.8x1.15 smd: 1(0.68,3.495) 2(0.68,6.445)
  silkscreen extent -0.68,-0.68 1.66,7.1
C_1210_3225Metric [mm]
  rrect22% 1.15x2.7 smd mask+0: 1(-1.475,0)
  rrect50% 1.15x2.7 smd mask+0: 2(1.475,0)
  silkscreen extent -0.83,-1.43 0.94,1.43
Coilcraft_XFL4020_4x4 [mm]
  rect 0.98x3.4 smd: 1(-1.185,0) 2(1.185,0)
  silkscreen extent -2.28,-2.28 2.28,2.28
CONN_105017-0001 [mm] "Molex Micro USB-B"
  rect 0.4x1.35 smd: 1(-1.3,1.35) 2(-0.65,1.35) 3(0,1.35) 4(0.65,1.35) 5(1.3,1.35)
  oval 1.2x1.9 hole 0.6 slot 1.3 at 0 deg: 6(-3.5,-1.35) 9(3.5,-1.35)
  rect 1.5x1.9 smd: 7(-1,-1.35) 8(1,-1.35)
  round 1.45 hole 0.85: 10(2.5,1.35) 11(-2.5,1.35)
  silkscreen extent -4.18,-3.78 4.18,3.78
CP2102N_QFN20_3x3_EP_Rev1p5 [mm]
  rect 0.3x0.3 smd: 1(-1.25,1.25) 6(-1.25,-1.25) 11(1.25,-1.25) 16(1.25,1.25)
  rect 0.9x0.3 smd: 2(-1.55,0.75) 3(-1.55,0.25) 4(-1.55,-0.25) 5(-1.55,-0.75) 12(1.55,-0.75) 13(1.55,-0.25) 14(1.55,0.25) 15(1.55,0.75)
  rect 0.3x0.9 smd: 7(-0.75,-1.55) 8(-0.25,-1.55) 9(0.25,-1.55) 10(0.75,-1.55) 17(0.75,1.55) 18(0.25,1.55) 19(-0.25,1.55) 20(-0.75,1.55)
  rect 1.8x1.8 smd paste+0: 21(0,0)
  rect 0.75x0.75 on Bottom Paste: P1(-0.475,-0.475) P2(-0.475,0.475) P3(0.475,-0.475) P4(0.475,0.475)
  silkscreen extent -2.08,-2.08 2.08,2.08
D_SMC [mm]
  rrect10% 2.5x3.3 smd mask+0: 1(-3.4,0)
  rrect50% 2.5x3.3 smd mask+0: 2(3.4,0)
  silkscreen extent -4.73,-3.38 4.73,3.38
DBV0005A-MFG [mm]
  rrect17% 1.1x0.6 smd paste+0 mask+0: 1(-1.3,0.95) 2(-1.3,0) 3(-1.3,-0.95) 4(1.3,-0.95) 5(1.3,0.95)
  silkscreen extent -0.64,-1.33 1.93,1.33
DCK0005A_N [mm] "SOT353, 5-Leads, Body 2x1.3mm, Pitch 0.65mm, Lead Span 2.1mm, IPC Medium Density"
  rrect25% 0.85x0.4 smd: 1(-1.125,0.65) 2(-1.125,0) 3(-1.125,-0.65) 4(1.125,-0.65) 5(1.125,0.65)
  silkscreen extent -0.59,-0.93 1.63,0.93
DGS0010A_L [mm] "TSSOP, 10-Leads, Body 3x3mm, Pitch 0.5mm, IPC High Density"
  oval 1.15x0.25 smd: 1(-2.125,1) 2(-2.125,0.5) 3(-2.125,0) 4(-2.125,-0.5) 5(-2.125,-1) 6(2.125,-1) 7(2.125,-0.5) 8(2.125,0) 9(2.125,0.5) 10(2.125,1)
  silkscreen extent -1.48,-1.21 1.48,1.2
DRR0012E-MFG [mm]
  rrect40% 0.62x0.25 smd paste+0 mask+0: 1(-1.39,1.25) 2(-1.39,0.75) 3(-1.39,0.25) 4(-1.39,-0.25) 5(-1.39,-0.75) 6(-1.39,-1.25) 7(1.39,-1.25) 8(1.39,-0.75) 9(1.39,-0.25) 10(1.39,0.25) 11(1.39,0.75) 12(1.39,1.25)
  rrect8% 1.3x2.5 smd paste-1000 mask+0: 13(0,0)
ESwitch_TL3301_GullWing_6x6 [mm] "E-Switch TL3301 series, 6 x 6 mm gull-wing tactile switch"
  rect 1.4x2.1 smd: 1(2.25,-4.55) 1(2.25,4.55) 2(-2.25,-4.55) 2(-2.25,4.55)
  silkscreen extent -3.38,-5.68 3.38,5.68
FP-CGA4J1X7R1H475K125AC_0805-MFG [mm]
  rrect13% 0.8x1.05 smd paste+0 mask+0: 1(-0.925,0) 2(0.925,0)
FP-ERJ-1GNF33R2C_0201-MFG [mm]
  rrect40% 0.25x0.3 smd paste+0 mask+0: 1(-0.3,0) 2(0.3,0)
  silkscreen extent -0.68,-0.68 0.68,0.68
FP-GCJ188C70J475KE02J_0603-MFG [mm]
  rrect13% 0.75x0.9 smd paste+0 mask+0: 1(-0.775,0) 2(0.775,0)
  silkscreen extent -1.23,-0.68 1.23,0.68
FP-GCM1555C1H3R9BA16D_0402-MFG [mm]
  rrect25% 0.4x0.5 smd paste+0 mask+0: 1(-0.4,0) 2(0.4,0)
  silkscreen extent -0.68,-0.68 0.68,0.68
FP-GD25B64CWAG_WSON8-IPC_C [mm]
  rrect23% 1.059x0.436 smd paste+0 mask+0: 1(-2.727,1.905)
  rrect100% 1.059x0.436 smd paste+0 mask+0: 2(-2.727,0.635) 3(-2.727,-0.635) 4(-2.727,-1.905) 5(2.727,-1.905) 6(2.727,-0.635) 7(2.727,0.635) 8(2.727,1.905)
  rrect3% 3.5x4.1 smd paste-1000 mask+0: 9(0,0)
  silkscreen extent -3.34,-3.08 3.34,3.08
FP-GRT155R70J105KE01D_0402-MFG [mm]
  rrect25% 0.4x0.5 smd paste+0 mask+0: 1(-0.4,0) 2(0.4,0)
  silkscreen extent -0.68,-0.68 0.68,0.68
FP-HCJ0603ZT0R00_0603-MFG [mm]
  rrect11% 1.3x0.92 smd paste+0 mask+0: 1(-0.95,0) 2(0.95,0)
  silkscreen extent -1.49,-0.68 1.68,0.68
FP-NFM18HC105C1C3D_0603-MFG [mm]
  rrect17% 0.6x0.7 smd paste+0 mask+0: 1(-0.8,0) 3(0.8,0)
  rrect25% 0.4x0.4 smd paste+0 mask+0: 2(0,0.4) 2(0,-0.4)
  silkscreen extent -1.18,-0.68 1.18,0.68
FP-NX2016SA-50M-STD-CZS-3_SMT4_2MM0_1MM6-MFG [mm]
  rrect13% 0.85x0.75 smd paste+0 mask+0: 1(-0.675,-0.525) 2(0.675,-0.525) 3(0.675,0.525) 4(-0.675,0.525)
  silkscreen extent -0.14,-0.98 0.14,0.98
"FP-TFM201610ALMAR24MTAA_0806 (2016 Metric)-MFG" [mm]
  rrect17% 0.6x1.6 smd paste+0 mask+0: 1(-0.9,0) 2(0.9,0)
  silkscreen extent -0.49,-0.88 0.49,0.88
FP-XAL4030-472MEC_SMD2-MFG [mm]
  rrect10% 0.98x3.4 smd paste+0 mask+0: 1(-1.185,0) 2(1.185,0)
  silkscreen extent -0.58,-1.78 0.58,1.78
FP-XEL4030-222MEC_SMT2_4MM0_4MM0-MFG [mm]
  rrect10% 0.98x3.4 smd paste+0 mask+0: 1(-1.185,0) 2(1.185,0)
ICM-42688-P_LGA14_2.5x3mm_P0.5mm [mm]
  rect 0.475x0.25 smd: 1(-1.012,-0.75) 2(-1.012,-0.25) 3(-1.012,0.25) 4(-1.012,0.75) 8(1.012,0.75) 9(1.012,0.25) 10(1.012,-0.25) 11(1.012,-0.75)
  rect 0.25x0.475 smd: 5(-0.5,1.262) 6(0,1.262) 7(0.5,1.262) 12(0.5,-1.262) 13(0,-1.262) 14(-0.5,-1.262)
  silkscreen extent -1.33,-1.58 1.33,1.58
JST_GH_SM06B-GHS-TB_1x06-1MP_P1.25mm_Horizontal [mm]
  rrect50% 1.7x0.6 smd: 1(-1.85,-3.125) 2(-1.85,-1.875) 3(-1.85,-0.625) 4(-1.85,0.625) 5(-1.85,1.875) 6(-1.85,3.125)
  rrect50% 2.7x1 smd: MP(1.35,-4.975) MP(1.35,4.975)
  silkscreen extent -3.28,-5.68 3.58,5.68
L_0603_1608Metric [mm]
  rrect25% 0.875x0.95 smd: 1(-0.787,0)
  rrect50% 0.875x0.95 smd: 2(0.787,0)
  silkscreen extent -1.3,-0.68 1.3,0.68
L_Coilcraft_XAL7070-XXX [mm]
  rrect13% 1.92x6.5 smd mask+0: 1(-2.41,0)
  rrect50% 1.92x6.5 smd mask+0: 2(2.41,0)
  silkscreen extent -3.78,-3.78 3.78,3.78
LQFP-176_24x24mm_P0.5mm [mm]
  rrect25% 1.5x0.3 smd: 1(-12.675,10.75) 2(-12.675,10.25) 3(-12.675,9.75) 4(-12.675,9.25) 5(-12.675,8.75) 6(-12.675,8.25) 7(-12.675,7.75) 8(-12.675,7.25) 9(-12.675,6.75) 10(-12.675,6.25) 11(-12.675,5.75) 12(-12.675,5.25) 13(-12.675,4.75) 14(-12.675,4.25) 15(-12.675,3.75) 16(-12.675,3.25) 17(-12.675,2.75) 18(-12.675,2.25) 19(-12.675,1.75) 20(-12.675,1.25) 21(-12.675,0.75) 22(-12.675,0.25) 23(-12.675,-0.25) 24(-12.675,-0.75) 25(-12.675,-1.25) 26(-12.675,-1.75) 27(-12.675,-2.25) 28(-12.675,-2.75) 29(-12.675,-3.25) 30(-12.675,-3.75) 31(-12.675,-4.25) 32(-12.675,-4.75) 33(-12.675,-5.25) 34(-12.675,-5.75) 35(-12.675,-6.25) 36(-12.675,-6.75) 37(-12.675,-7.25) 38(-12.675,-7.75) 39(-12.675,-8.25) 40(-12.675,-8.75) 41(-12.675,-9.25) 42(-12.675,-9.75) 43(-12.675,-10.25) 44(-12.675,-10.75) 89(12.675,-10.75) 90(12.675,-10.25) 91(12.675,-9.75) 92(12.675,-9.25) 93(12.675,-8.75) 94(12.675,-8.25) 95(12.675,-7.75) 96(12.675,-7.25) 97(12.675,-6.75) 98(12.675,-6.25) 99(12.675,-5.75) 100(12.675,-5.25) 101(12.675,-4.75) 102(12.675,-4.25) 103(12.675,-3.75) 104(12.675,-3.25) 105(12.675,-2.75) 106(12.675,-2.25) 107(12.675,-1.75) 108(12.675,-1.25) 109(12.675,-0.75) 110(12.675,-0.25) 111(12.675,0.25) 112(12.675,0.75) 113(12.675,1.25) 114(12.675,1.75) 115(12.675,2.25) 116(12.675,2.75) 117(12.675,3.25) 118(12.675,3.75) 119(12.675,4.25) 120(12.675,4.75) 121(12.675,5.25) 122(12.675,5.75) 123(12.675,6.25) 124(12.675,6.75) 125(12.675,7.25) 126(12.675,7.75) 127(12.675,8.25) 128(12.675,8.75) 129(12.675,9.25) 130(12.675,9.75) 131(12.675,10.25) 132(12.675,10.75)
  rrect25% 0.3x1.5 smd: 45(-10.75,-12.675) 46(-10.25,-12.675) 47(-9.75,-12.675) 48(-9.25,-12.675) 49(-8.75,-12.675) 50(-8.25,-12.675) 51(-7.75,-12.675) 52(-7.25,-12.675) 53(-6.75,-12.675) 54(-6.25,-12.675) 55(-5.75,-12.675) 56(-5.25,-12.675) 57(-4.75,-12.675) 58(-4.25,-12.675) 59(-3.75,-12.675) 60(-3.25,-12.675) 61(-2.75,-12.675) 62(-2.25,-12.675) 63(-1.75,-12.675) 64(-1.25,-12.675) 65(-0.75,-12.675) 66(-0.25,-12.675) 67(0.25,-12.675) 68(0.75,-12.675) 69(1.25,-12.675) 70(1.75,-12.675) 71(2.25,-12.675) 72(2.75,-12.675) 73(3.25,-12.675) 74(3.75,-12.675) 75(4.25,-12.675) 76(4.75,-12.675) 77(5.25,-12.675) 78(5.75,-12.675) 79(6.25,-12.675) 80(6.75,-12.675) 81(7.25,-12.675) 82(7.75,-12.675) 83(8.25,-12.675) 84(8.75,-12.675) 85(9.25,-12.675) 86(9.75,-12.675) 87(10.25,-12.675) 88(10.75,-12.675) 133(10.75,12.675) 134(10.25,12.675) 135(9.75,12.675) 136(9.25,12.675) 137(8.75,12.675) 138(8.25,12.675) 139(7.75,12.675) 140(7.25,12.675) 141(6.75,12.675) 142(6.25,12.675) 143(5.75,12.675) 144(5.25,12.675) 145(4.75,12.675) 146(4.25,12.675) 147(3.75,12.675) 148(3.25,12.675) 149(2.75,12.675) 150(2.25,12.675) 151(1.75,12.675) 152(1.25,12.675) 153(0.75,12.675) 154(0.25,12.675) 155(-0.25,12.675) 156(-0.75,12.675) 157(-1.25,12.675) 159(-2.25,12.675) 160(-2.75,12.675) 161(-3.25,12.675) 162(-3.75,12.675) 163(-4.25,12.675) 164(-4.75,12.675) 165(-5.25,12.675) 166(-5.75,12.675) 167(-6.25,12.675) 168(-6.75,12.675) 169(-7.25,12.675) 170(-7.75,12.675) 171(-8.25,12.675) 172(-8.75,12.675) 173(-9.25,12.675) 174(-9.75,12.675) 175(-10.25,12.675) 176(-10.75,12.675)
  rrect50% 0.3x1.5 smd: 158(-1.75,12.675)
  silkscreen extent -13.5,-13.5 13.5,13.5
Molex_43045-0600_RA_THT_6P [mm]
  rrect50% 1.5x1.5 hole 1.02: 1(0,0)
  round 1.5 hole 1.02: 2(3,0) 3(6,0) 4(0,-3) 5(3,-3) 6(6,-3)
  round 3 hole 3: Un1(3,4.32)
  silkscreen extent -3.4,-4.08 9.4,9
Molex_43650-0200_RA_THT_2P [mm]
  rrect17% 1.5x2.02 hole 1.02: 1(0,0)
  rrect50% 1.5x2.02 hole 1.02: 2(3,0)
  round 3 hole 3: Un1(1.5,4.32)
  silkscreen extent -3.4,-1.09 6.4,9
Net-Tie_50milWide_30milLong [mil] "50mil net tie, no solder mask opening, no solder paste"
  rect 30x50 smd paste-20 mask-20: 1(-15,0) 2(15,0)
Oscillator_SMD_ECS_2520MV-xxx-xx-4Pin_2.5x2.0mm [mm]
  rrect25% 0.8x0.9 smd: 1(-0.725,0.925) 3(0.725,-0.925) 4(0.725,0.925)
  rrect50% 0.8x0.9 smd: 2(-0.725,-0.925)
  silkscreen extent -1.33,-1.45 1.33,1.46
R_0402_1005Metric#1 [mm]
  rrect50% 0.54x0.64 smd: 1(-0.51,0) 2(0.51,0)
  silkscreen extent -0.86,-0.68 0.86,0.68
R_0402_1005Metric#2 [mm]
  rrect50% 0.54x0.64 smd: 1(-0.51,0)
  rrect25% 0.54x0.64 smd: 2(0.51,0)
  silkscreen extent -0.86,-0.68 0.86,0.68
R_0402_1005Metric#3 [mm]
  rrect25% 0.54x0.64 smd: 1(-0.51,0)
  rrect50% 0.54x0.64 smd: 2(0.51,0)
  silkscreen extent -0.86,-0.68 0.86,0.68
R_0603_1608Metric#1 [mm]
  rrect25% 0.8x0.95 smd: 1(-0.825,0)
  rrect50% 0.8x0.95 smd: 2(0.825,0)
  silkscreen extent -1.31,0.5 1.3,0.68
R_0603_1608Metric#2 [mm]
  rrect50% 0.8x0.95 smd: 1(-0.825,0)
  rrect25% 0.8x0.95 smd: 2(0.825,0)
  silkscreen extent -1.31,-0.68 1.3,0.68
R_0603_1608Metric#3 [mm]
  rrect50% 0.95x0.8 smd: 1(0,-0.825) 2(0,0.825)
  silkscreen extent -0.68,-1.3 0.68,1.31
R_0603_1608Metric#4 [mm]
  rrect50% 0.8x0.95 smd: 1(-0.825,0) 2(0.825,0)
  silkscreen extent -1.3,-0.68 1.31,0.68
RXV0028A-MFG [mm]
  round 0.195 smd paste+0 mask+0: 1(-1.573,2.03) 9(-1.573,-2.03)
  rrect40% 0.8x0.25 smd paste+0 mask+0: 2(-2.05,1.5) 8(-2.05,-1.5) 16(2.05,-1.5) 22(2.05,1.5)
  rrect40% 0.725x0.25 smd paste+0 mask+0: 3(-2.087,1) 7(-2.087,-1) 17(2.087,-1) 21(2.087,1)
  rrect40% 0.85x0.25 smd paste+0 mask+0: 4(-2.025,0.5) 6(-2.025,-0.5) 18(2.025,-0.5) 20(2.025,0.5)
  rrect40% 0.6x0.25 smd paste+0 mask+0: 5(-1.95,0) 5-19(0,0) 19(1.95,0)
  rrect40% 0.25x1.175 smd paste+0 mask+0: 10(-1,-2.113) 14(1,-2.113) 24(1,2.113) 28(-1,2.113)
  rrect40% 0.25x1.55 smd paste-1000 mask+0: 11(-0.5,-1.925) 13(0.5,-1.925) 25(0.5,1.925) 27(-0.5,1.925)
  rrect40% 0.25x1.9 smd paste-1000 mask+0: 12(0,-1.75) 26(0,1.75)
  round 0.243 smd paste+0 mask+0: 15(1.53,-2.03) 23(1.53,2.03)
  Top Layer region: 2.45,2.075 2.45,2.075 2.449,2.085 2.446,2.094 2.442,2.103 2.435,2.11 2.428,2.117 2.419,2.121 2.41,2.124 2.4,2.125 2.4,2.125 1.625,2.125 1.625,2.65 1.624,2.66 1.621,2.669 1.617,2.678 1.61,2.685 1.603,2.692 1.594,2.696 1.585,2.699 1.575,2.7 1.575,2.7 1.425,2.7 1.415,2.699 1.406,2.696 1.397,2.692 1.39,2.685 1.383,2.678 1.379,2.669 1.376,2.66 1.375,2.65 1.375,2.65 1.375,1.925 1.376,1.915 1.379,1.906 1.383,1.897 1.39,1.89 1.397,1.883 1.406,1.879 1.415,1.876 1.425,1.875 1.425,1.875 2.4,1.875 2.41,1.876 2.419,1.879 2.428,1.883 2.435,1.89 2.442,1.897 2.446,1.906 2.449,1.915 2.45,1.925 2.45,1.925
  Top Layer region: 2.45,-2.075 2.45,-2.075 2.449,-2.085 2.446,-2.094 2.442,-2.103 2.435,-2.11 2.428,-2.117 2.419,-2.121 2.41,-2.124 2.4,-2.125 2.4,-2.125 1.625,-2.125 1.625,-2.65 1.624,-2.66 1.621,-2.669 1.617,-2.678 1.61,-2.685 1.603,-2.692 1.594,-2.696 1.585,-2.699 1.575,-2.7 1.575,-2.7 1.425,-2.7 1.415,-2.699 1.406,-2.696 1.397,-2.692 1.39,-2.685 1.383,-2.678 1.379,-2.669 1.376,-2.66 1.375,-2.65 1.375,-2.65 1.375,-1.925 1.376,-1.915 1.379,-1.906 1.383,-1.897 1.39,-1.89 1.397,-1.883 1.406,-1.879 1.415,-1.876 1.425,-1.875 1.425,-1.875 2.4,-1.875 2.41,-1.876 2.419,-1.879 2.428,-1.883 2.435,-1.89 2.442,-1.897 2.446,-1.906 2.449,-1.915 2.45,-1.925 2.45,-1.925
  Top Layer region: -2.45,2.075 -2.45,2.075 -2.449,2.085 -2.446,2.094 -2.442,2.103 -2.435,2.11 -2.428,2.117 -2.419,2.121 -2.41,2.124 -2.4,2.125 -2.4,2.125 -1.625,2.125 -1.625,2.65 -1.624,2.66 -1.621,2.669 -1.617,2.678 -1.61,2.685 -1.603,2.692 -1.594,2.696 -1.585,2.699 -1.575,2.7 -1.575,2.7 -1.425,2.7 -1.415,2.699 -1.406,2.696 -1.397,2.692 -1.39,2.685 -1.383,2.678 -1.379,2.669 -1.376,2.66 -1.375,2.65 -1.375,1.925 -1.376,1.915 -1.379,1.906 -1.383,1.897 -1.39,1.89 -1.397,1.883 -1.406,1.879 -1.415,1.876 -1.425,1.875 -1.425,1.875 -2.4,1.875 -2.41,1.876 -2.419,1.879 -2.428,1.883 -2.435,1.89 -2.442,1.897 -2.446,1.906 -2.449,1.915 -2.45,1.925
  Top Layer region: -2.45,-2.075 -2.45,-2.075 -2.449,-2.085 -2.446,-2.094 -2.442,-2.103 -2.435,-2.11 -2.428,-2.117 -2.419,-2.121 -2.41,-2.124 -2.4,-2.125 -2.4,-2.125 -1.625,-2.125 -1.625,-2.65 -1.624,-2.66 -1.621,-2.669 -1.617,-2.678 -1.61,-2.685 -1.603,-2.692 -1.594,-2.696 -1.585,-2.699 -1.575,-2.7 -1.575,-2.7 -1.425,-2.7 -1.415,-2.699 -1.406,-2.696 -1.397,-2.692 -1.39,-2.685 -1.383,-2.678 -1.379,-2.669 -1.376,-2.66 -1.375,-2.65 -1.375,-1.925 -1.376,-1.915 -1.379,-1.906 -1.383,-1.897 -1.39,-1.89 -1.397,-1.883 -1.406,-1.879 -1.415,-1.876 -1.425,-1.875 -1.425,-1.875 -2.4,-1.875 -2.41,-1.876 -2.419,-1.879 -2.428,-1.883 -2.435,-1.89 -2.442,-1.897 -2.446,-1.906 -2.449,-1.915 -2.45,-1.925
  Top Layer region: -2.466,0.073 -2.466,0.073 -2.465,0.083 -2.462,0.093 -2.458,0.101 -2.451,0.109 -2.444,0.115 -2.435,0.12 -2.426,0.123 -2.416,0.123 -2.416,0.123 -0.641,0.123 -0.641,0.398 0.609,0.398 0.609,0.123 2.384,0.123 2.394,0.123 2.403,0.12 2.412,0.115 2.419,0.109 2.426,0.101 2.43,0.093 2.433,0.083 2.434,0.073 2.434,0.073 2.434,-0.077 2.433,-0.086 2.43,-0.096 2.426,-0.104 2.419,-0.112 2.412,-0.118 2.403,-0.123 2.394,-0.126 2.384,-0.127 2.384,-0.127 0.609,-0.127 0.609,-0.402 -0.641,-0.402 -0.641,-0.127 -2.416,-0.127 -2.426,-0.126 -2.435,-0.123 -2.444,-0.118 -2.451,-0.112 -2.458,-0.104 -2.462,-0.096 -2.465,-0.086 -2.466,-0.077 -2.466,-0.077
  silkscreen extent -2.58,-2.78 2.58,2.78
SM_RADIAL_6.3BMM [mm] "Nichicon 6.3x7.7"
  rect 3.5x1.6 smd: 1(-2.7,0) 2(2.7,0)
  silkscreen extent -0.79,-0.88 0.79,0.88
SOT-23 [mm] "JEDEC TO-236 AB, three-pad SOT-23"
  rect 1.475x0.6 smd: 1(-0.937,-0.95) 2(-0.937,0.95) 3(0.937,0)
  silkscreen extent -1.75,-1.33 1.76,1.33
TagConnect_TC2030_NL [mil]
  round 31 smd: 1(-50,-25) 2(-50,25) 3(0,-25) 4(0,25) 5(50,-25) 6(50,25)
  round 39 hole 39: Un1(-100,0) Un2(100,40) Un3(100,-40)
  silkscreen extent -123,-63 123,63
TestPoint_Pad_D1.0mm [mm]
  round 1 smd: 1(0,0)
  silkscreen extent -0.68,-0.68 0.68,0.68
TestPoint_Pad_D1.5mm [mm]
  round 1.5 smd paste+0: 1(0,0)
  silkscreen extent -0.83,-0.83 0.83,0.83
Texas_DRB0008A [mm]
  rrect50% 0.6x0.31 smd: 1(-1.4,0.975) 2(-1.4,0.325) 3(-1.4,-0.325) 4(-1.4,-0.975) 5(1.4,-0.975) 6(1.4,-0.325) 7(1.4,0.325) 8(1.4,0.975)
  round 0.5 hole 0.2: 9(-0.5,0) 9(0,-0.625) 9(0,0.625) 9(0.5,0)
  rrect50% 0.23x1.025 smd: 9(-0.325,-1.188) 9(-0.325,1.188) 9(0.325,-1.188) 9(0.325,1.188)
  rrect50% 1.5x1.75 smd: 9(0,0)
  rrect50% 1.5x1.75 smd far side: 9(0,0)
  rrect50% 0.23x0.725 on Bottom Paste: Un1(-0.325,1.337) Un2(-0.325,-1.337) Un4(0.325,1.337) Un5(0.325,-1.337)
  rrect50% 1.34x1.55 on Bottom Paste: Un3(0,0)
  silkscreen extent -1.78,-1.78 1.78,1.78
Texas_RGE0024C_VQFN-24-1EP_4x4mm_P0.5mm_EP2.1x2.1mm [mm]
  rrect25% 0.875x0.25 smd mask+0: 1(-1.937,1.25) 2(-1.937,0.75) 3(-1.937,0.25) 4(-1.937,-0.25) 5(-1.937,-0.75) 6(-1.937,-1.25) 13(1.937,-1.25) 14(1.937,-0.75) 15(1.937,-0.25) 16(1.937,0.25) 17(1.937,0.75) 18(1.937,1.25)
  rrect25% 0.25x0.875 smd mask+0: 7(-1.25,-1.937) 8(-0.75,-1.937) 9(-0.25,-1.937) 10(0.25,-1.937) 11(0.75,-1.937) 12(1.25,-1.937) 19(1.25,1.937) 20(0.75,1.937) 21(0.25,1.937) 22(-0.25,1.937) 23(-0.75,1.937) 24(-1.25,1.937)
  rect 2.1x2.1 smd paste-2.1 mask+0: 25(0,0)
  rrect50% 0.85x0.85 on Bottom Paste mask-0.85: Un1(-0.525,0.525) Un2(-0.525,-0.525) Un3(0.525,0.525) Un4(0.525,-0.525)
  silkscreen extent -2.45,-2.45 2.45,2.45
